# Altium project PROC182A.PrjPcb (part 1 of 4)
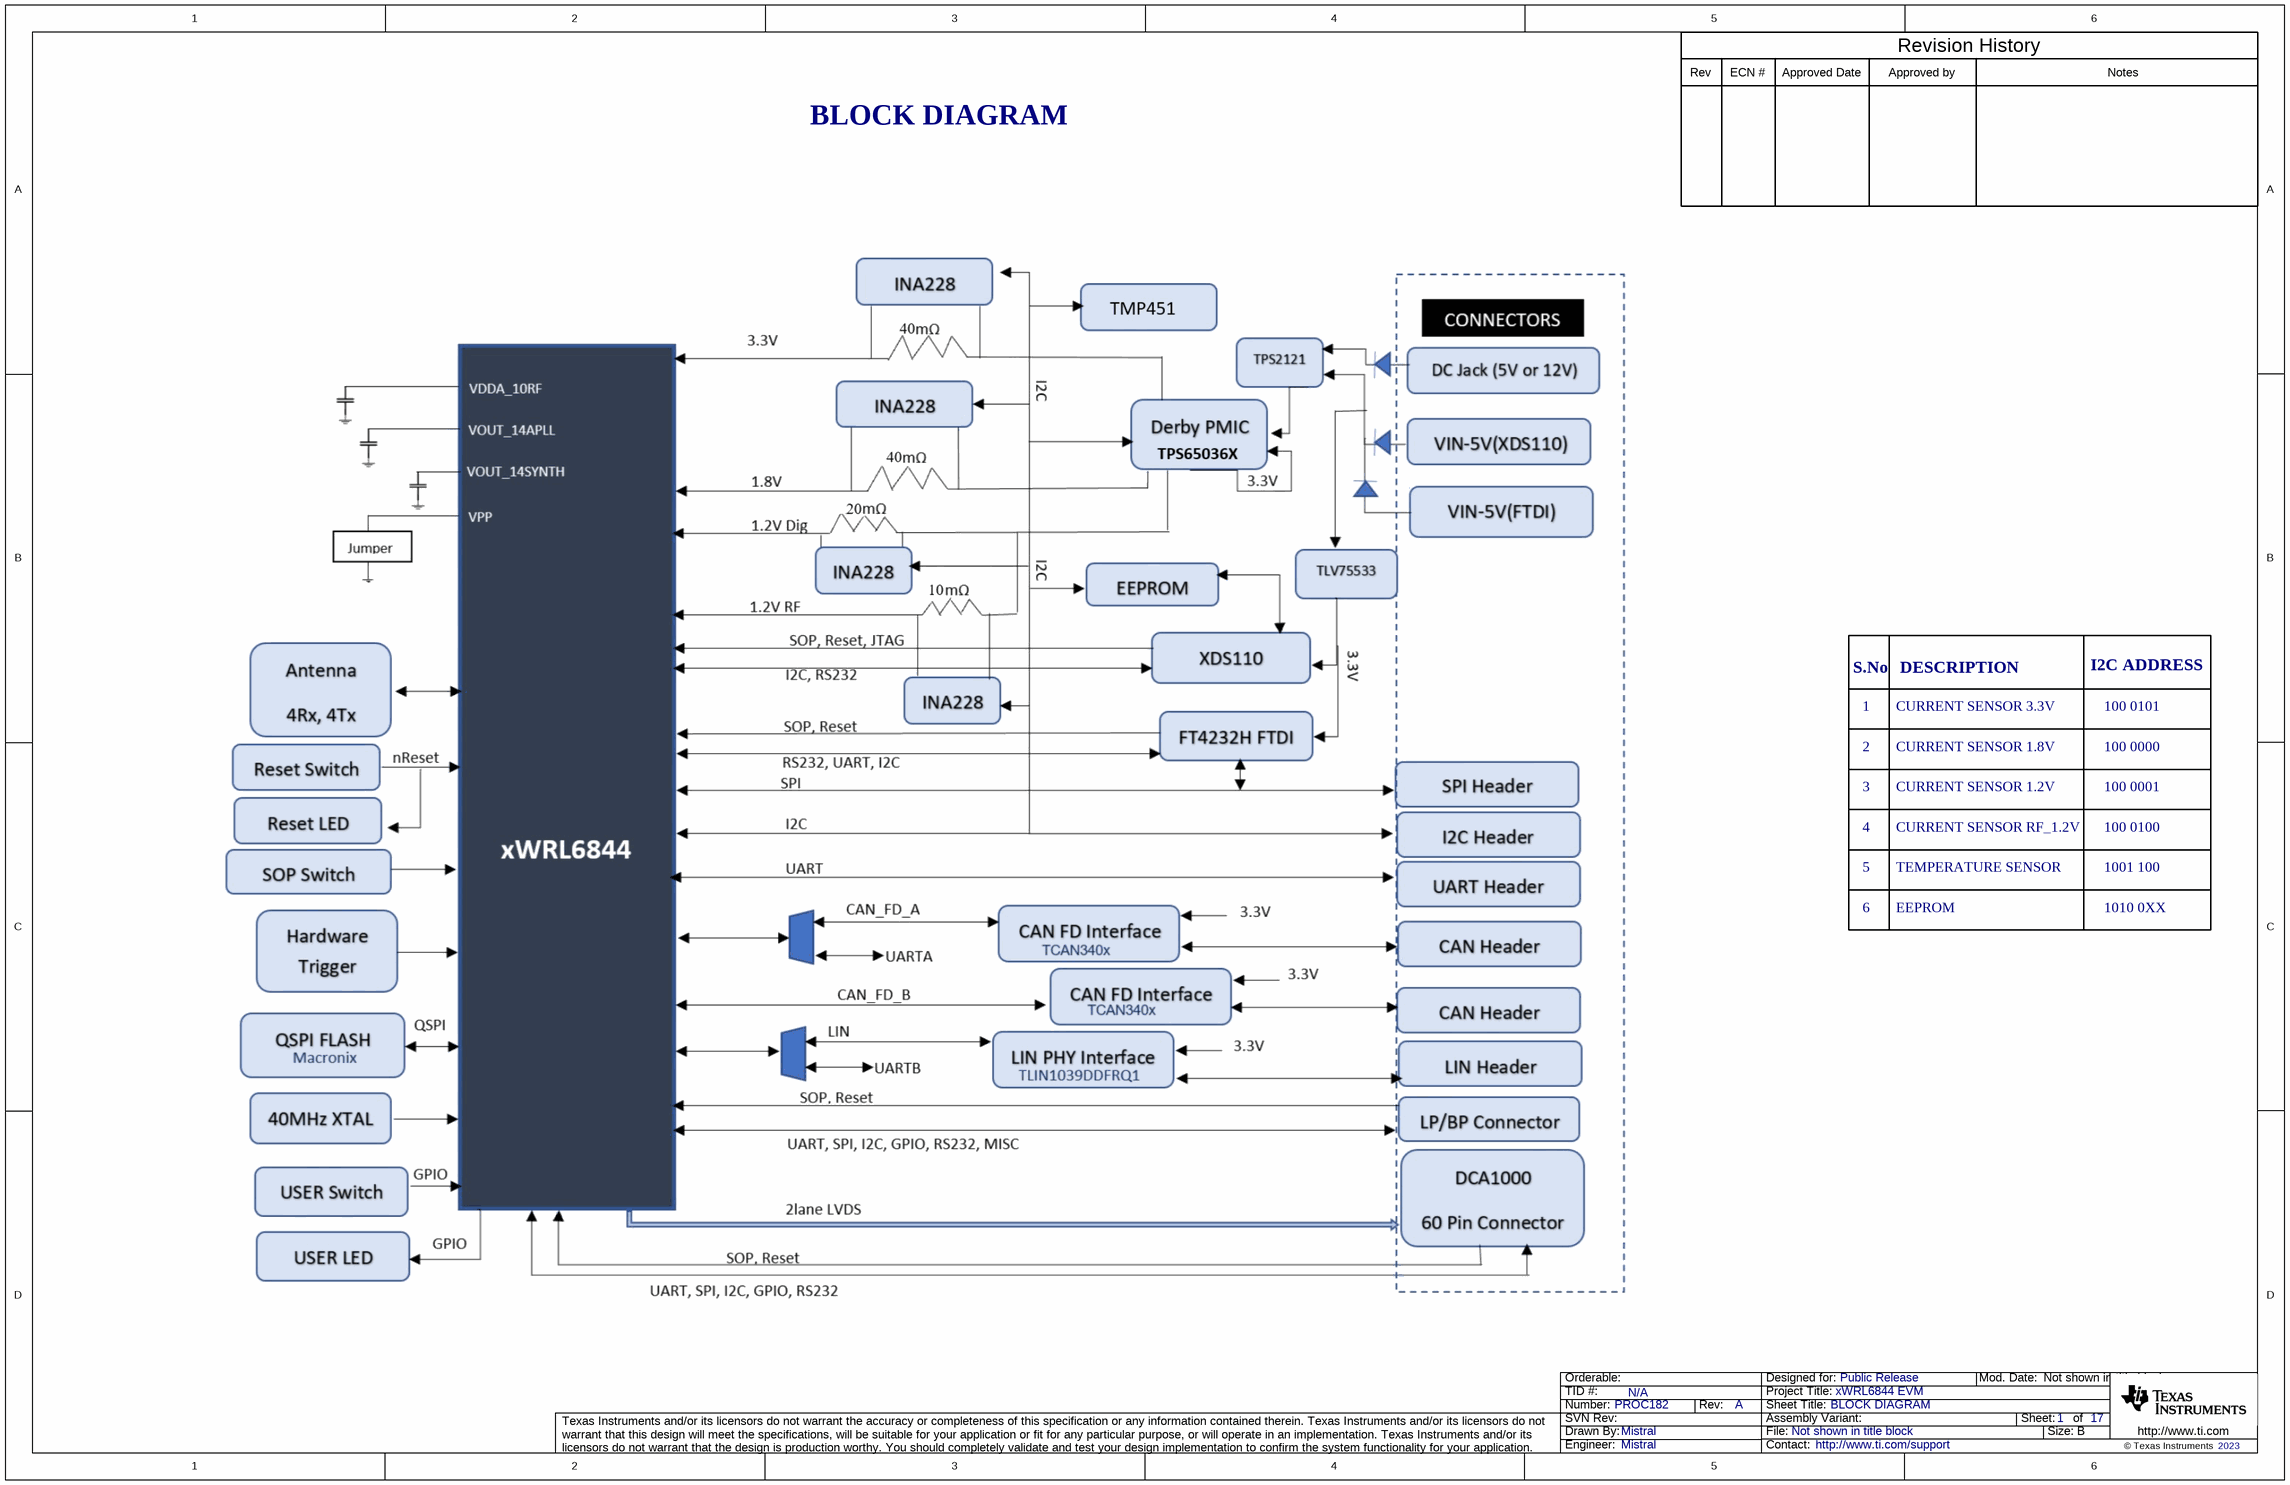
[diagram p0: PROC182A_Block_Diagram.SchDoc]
CopyrightYear: 2023; PCB_Layout: Mistral; PCB_Rev: A; PRJ_Customer: Public Release; PRJ_Engineer: Mistral; PRJ_Number: PROC182; PRJ_Title: xWRL6844 EVM; SCH_Rev: A; TechSupport: http://www.ti.com/support; TID: N/A
17 sheets, 568 parts. Net scope: flat (ports and power ports of the same name join across sheets).
Board file: PROC182A_PCB.PcbDoc
Sheets:
  PROC182A_Block_Diagram.SchDoc
  PROC182A_MUX_Block_Diagram.SchDoc
  PROC182A_Table_Of_Contents.SchDoc
  PROC182A_USB_PWR_DC_Jack_Switch.SchDoc
  PROC182A_PMIC.SchDoc
  PROC182A_Chip.SchDoc
  PROC182A_Decoupling_caps- QSPI Flash.SchDoc
  PROC182A_Temp_Current_sensors_EPROM.SchDoc
  PROC182A_Analog_Mux_SOP_Ctrl.SchDoc
  PROC182A_Analog_MUX_SPI.SchDoc
  PROC182A_XDS110_Interface.SchDoc
  PROC182A_MUX_CAN_FD.SchDoc
  PROC182A_CAN_LIN_PHY_Interface.SchDoc
  PROC182A_FTDI.SchDoc
  PROC182A_DCA1000_Connector_Reset.SchDoc
  PROC182A_I2C_SPI_Connector.SchDoc
  PROC182A_EVM_Hardware.SchDoc

## Sheet PROC182A_Block_Diagram.SchDoc: BLOCK DIAGRAM
size 431 x 279 mm; Date: Not shown in title block; ApprovedBy: Not shown in title block; CheckedBy: Not shown in title block; Author: Not shown in title block; CompanyName: Not shown in title block; DrawnBy: Mistral; Organization: Not shown in title block; Address1: Not shown in title block; Address2: Not shown in title block; Address3: Not shown in title block; Address4: Not shown in title block; DocumentNumber: 1; Revision: Use project parameter SCH_Rev; SheetNumber: 1; SheetTotal: 17; PageSetup: Record=PageOptions¦CenterHorizontal=True¦CenterVertical=True¦PrintScale=1.00¦XCorrection=1.00¦YCorrection=1.00¦PrintKind=0¦BorderSize=5000000¦LeftOffset=0¦BottomOffset=0¦Orientation=2¦PaperLength=1000¦PaperWidth=1000¦Scale=100¦PaperSource=15¦PrintQuality=600¦MediaType=1¦DitherType=10¦PaperKind=Letter¦PrintScaleMode=1

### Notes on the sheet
- Rev
- ECN #
- Approved Date
- Approved by
- Revision History
- Notes
- BLOCK DIAGRAM
- S.No
- DESCRIPTION
- I2C ADDRESS
- 1
- 2
- CURRENT SENSOR 3.3V
- CURRENT SENSOR 1.8V
- 100 0000
- 100 0101
- 3
- 4
- CURRENT SENSOR 1.2V
- CURRENT SENSOR RF_1.2V
- 100 0001
- 100 0100
- 5
- TEMPERATURE SENSOR
- 1001 100
- 6
- EEPROM
- 1010 0XX

## Sheet PROC182A_MUX_Block_Diagram.SchDoc: MUX BLOCK DIAGRAM
size 431 x 279 mm; Date: Not shown in title block; ApprovedBy: Not shown in title block; CheckedBy: Not shown in title block; Author: Not shown in title block; CompanyName: Not shown in title block; DrawnBy: Mistral; Engineer: Not shown in title block; Organization: Not shown in title block; Address1: Not shown in title block; Address2: Not shown in title block; Address3: Not shown in title block; Address4: Not shown in title block; DocumentNumber: 2; Revision: Use project parameter SCH_Rev; SheetNumber: 2; SheetTotal: 17; PageSetup: Record=PageOptions¦CenterHorizontal=True¦CenterVertical=True¦PrintScale=1.00¦XCorrection=1.00¦YCorrection=1.00¦PrintKind=0¦BorderSize=5000000¦LeftOffset=0¦BottomOffset=0¦Orientation=2¦PaperLength=1000¦PaperWidth=1000¦Scale=100¦PaperSource=15¦PrintQuality=600¦MediaType=1¦DitherType=10¦PaperKind=Letter¦PrintScaleMode=1
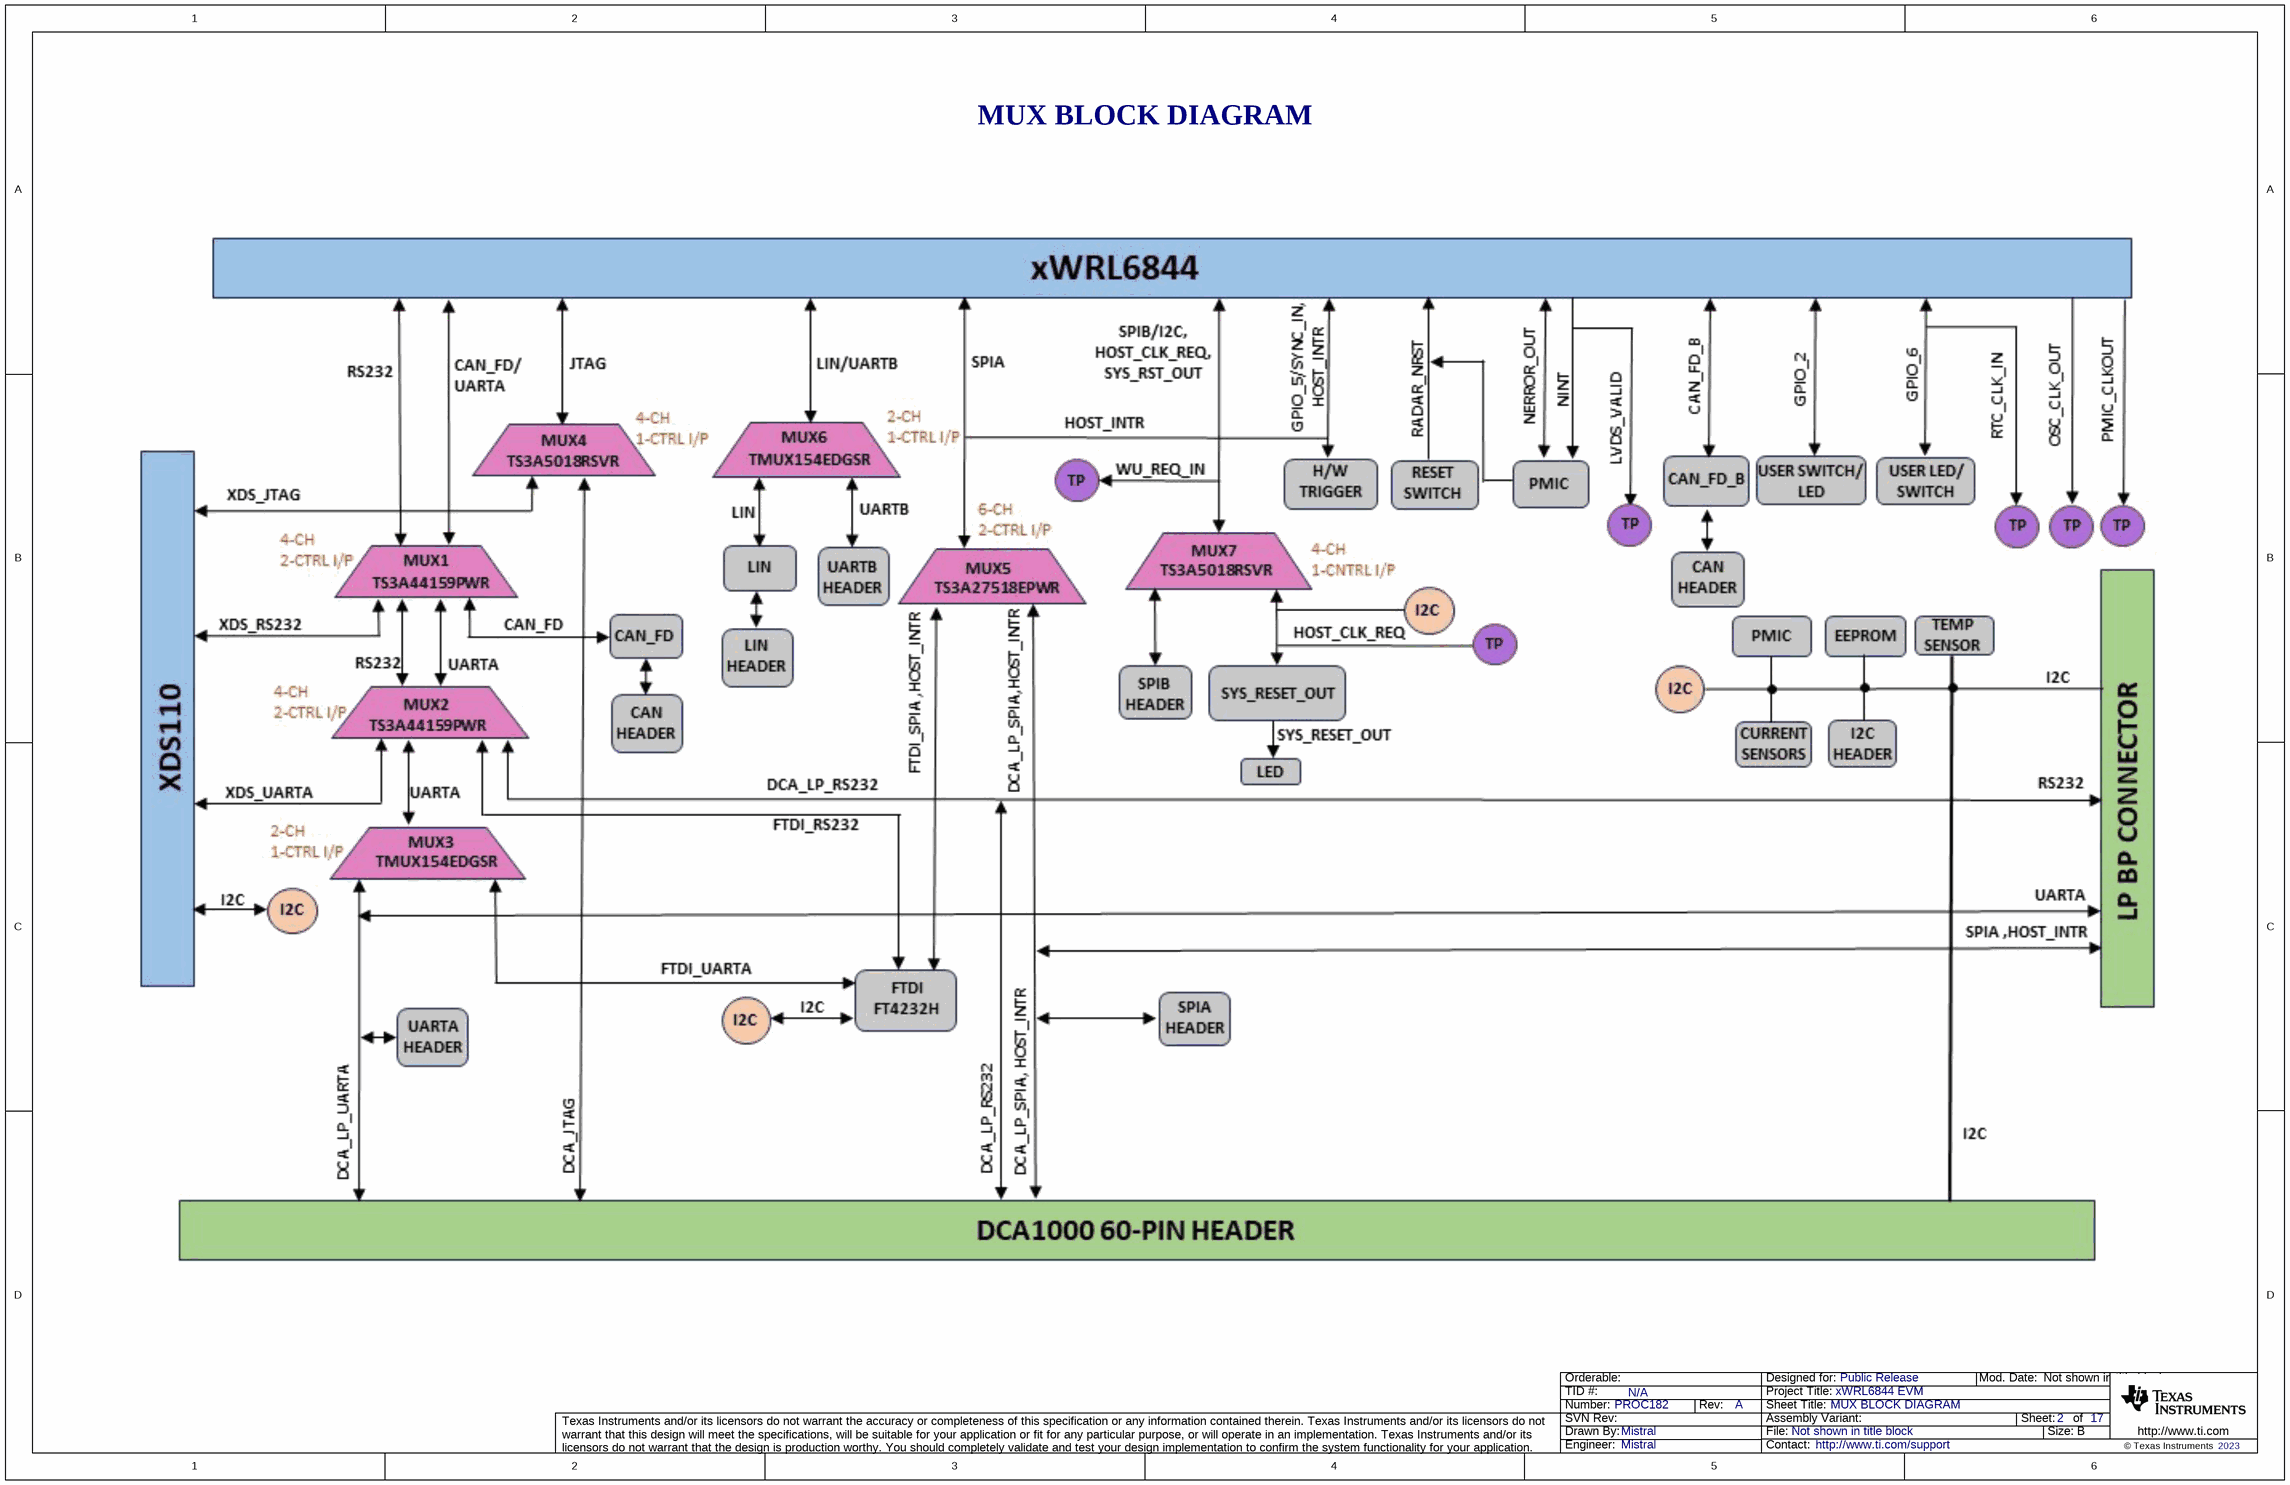
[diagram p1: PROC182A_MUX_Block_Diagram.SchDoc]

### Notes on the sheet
- MUX BLOCK DIAGRAM

## Sheet PROC182A_Table_Of_Contents.SchDoc: TABLE OF CONTENTS
size 431 x 279 mm; Date: Not shown in title block; ApprovedBy: Not shown in title block; CheckedBy: Not shown in title block; Author: Not shown in title block; CompanyName: Not shown in title block; DrawnBy: Mistral; Engineer: Not shown in title block; Organization: Not shown in title block; Address1: Not shown in title block; Address2: Not shown in title block; Address3: Not shown in title block; Address4: Not shown in title block; DocumentNumber: 3; Revision: Use project parameter SCH_Rev; SheetNumber: 3; SheetTotal: 16; PageSetup: Record=PageOptions¦CenterHorizontal=True¦CenterVertical=True¦PrintScale=1.00¦XCorrection=1.00¦YCorrection=1.00¦PrintKind=0¦BorderSize=5000000¦LeftOffset=0¦BottomOffset=0¦Orientation=2¦PaperLength=1000¦PaperWidth=1000¦Scale=100¦PaperSource=15¦PrintQuality=600¦MediaType=1¦DitherType=10¦PaperKind=Letter¦PrintScaleMode=1
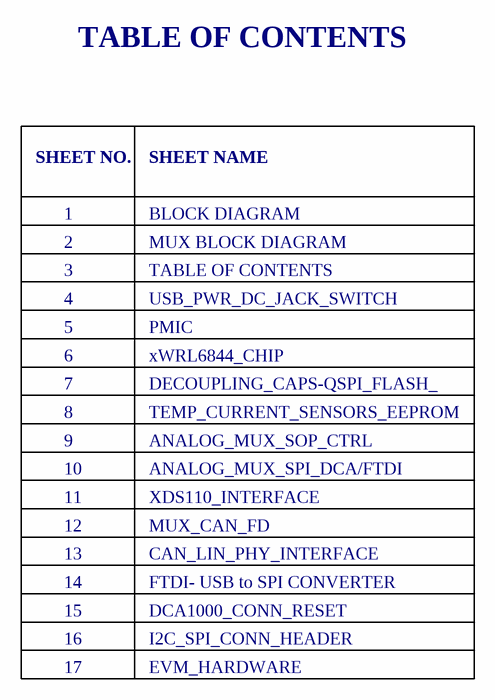
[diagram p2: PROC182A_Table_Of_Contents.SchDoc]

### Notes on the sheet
- TABLE OF CONTENTS
- SHEET NO.
- SHEET NAME
- 1
- 2
- 3
- BLOCK DIAGRAM
- MUX BLOCK DIAGRAM
- 4
- 5
- USB_PWR_DC_JACK_SWITCH
- PMIC
- 7
- 8
- 6
- DECOUPLING_CAPS-QSPI_FLASH_
- TEMP_CURRENT_SENSORS_EEPROM
- xWRL6844_CHIP
- 10
- 9
- ANALOG_MUX_SOP_CTRL
- ANALOG_MUX_SPI_DCA/FTDI
- 11
- 12
- 13
- XDS110_INTERFACE
- CAN_LIN_PHY_INTERFACE
- MUX_CAN_FD
- 14
- 15
- DCA1000_CONN_RESET
- FTDI- USB to SPI CONVERTER
- 16
- 17
- I2C_SPI_CONN_HEADER
- EVM_HARDWARE

## Sheet PROC182A_USB_PWR_DC_Jack_Switch.SchDoc: USB_PWR_DC_JACK_SWITCH
size 431 x 279 mm; Date: Not shown in title block; ApprovedBy: Not shown in title block; CheckedBy: Not shown in title block; Author: Not shown in title block; CompanyName: Not shown in title block; DrawnBy: Mistral; Engineer: Not shown in title block; Organization: Not shown in title block; Address1: Not shown in title block; Address2: Not shown in title block; Address3: Not shown in title block; Address4: Not shown in title block; DocumentNumber: 4; Revision: Use project parameter SCH_Rev; SheetNumber: 4; SheetTotal: 17; PageSetup: Record=PageOptions¦CenterHorizontal=True¦CenterVertical=True¦PrintScale=1.00¦XCorrection=1.00¦YCorrection=1.00¦PrintKind=0¦BorderSize=5000000¦LeftOffset=0¦BottomOffset=0¦Orientation=2¦PaperLength=1000¦PaperWidth=1000¦Scale=100¦PaperSource=15¦PrintQuality=600¦MediaType=1¦DitherType=10¦PaperKind=Letter¦PrintScaleMode=1
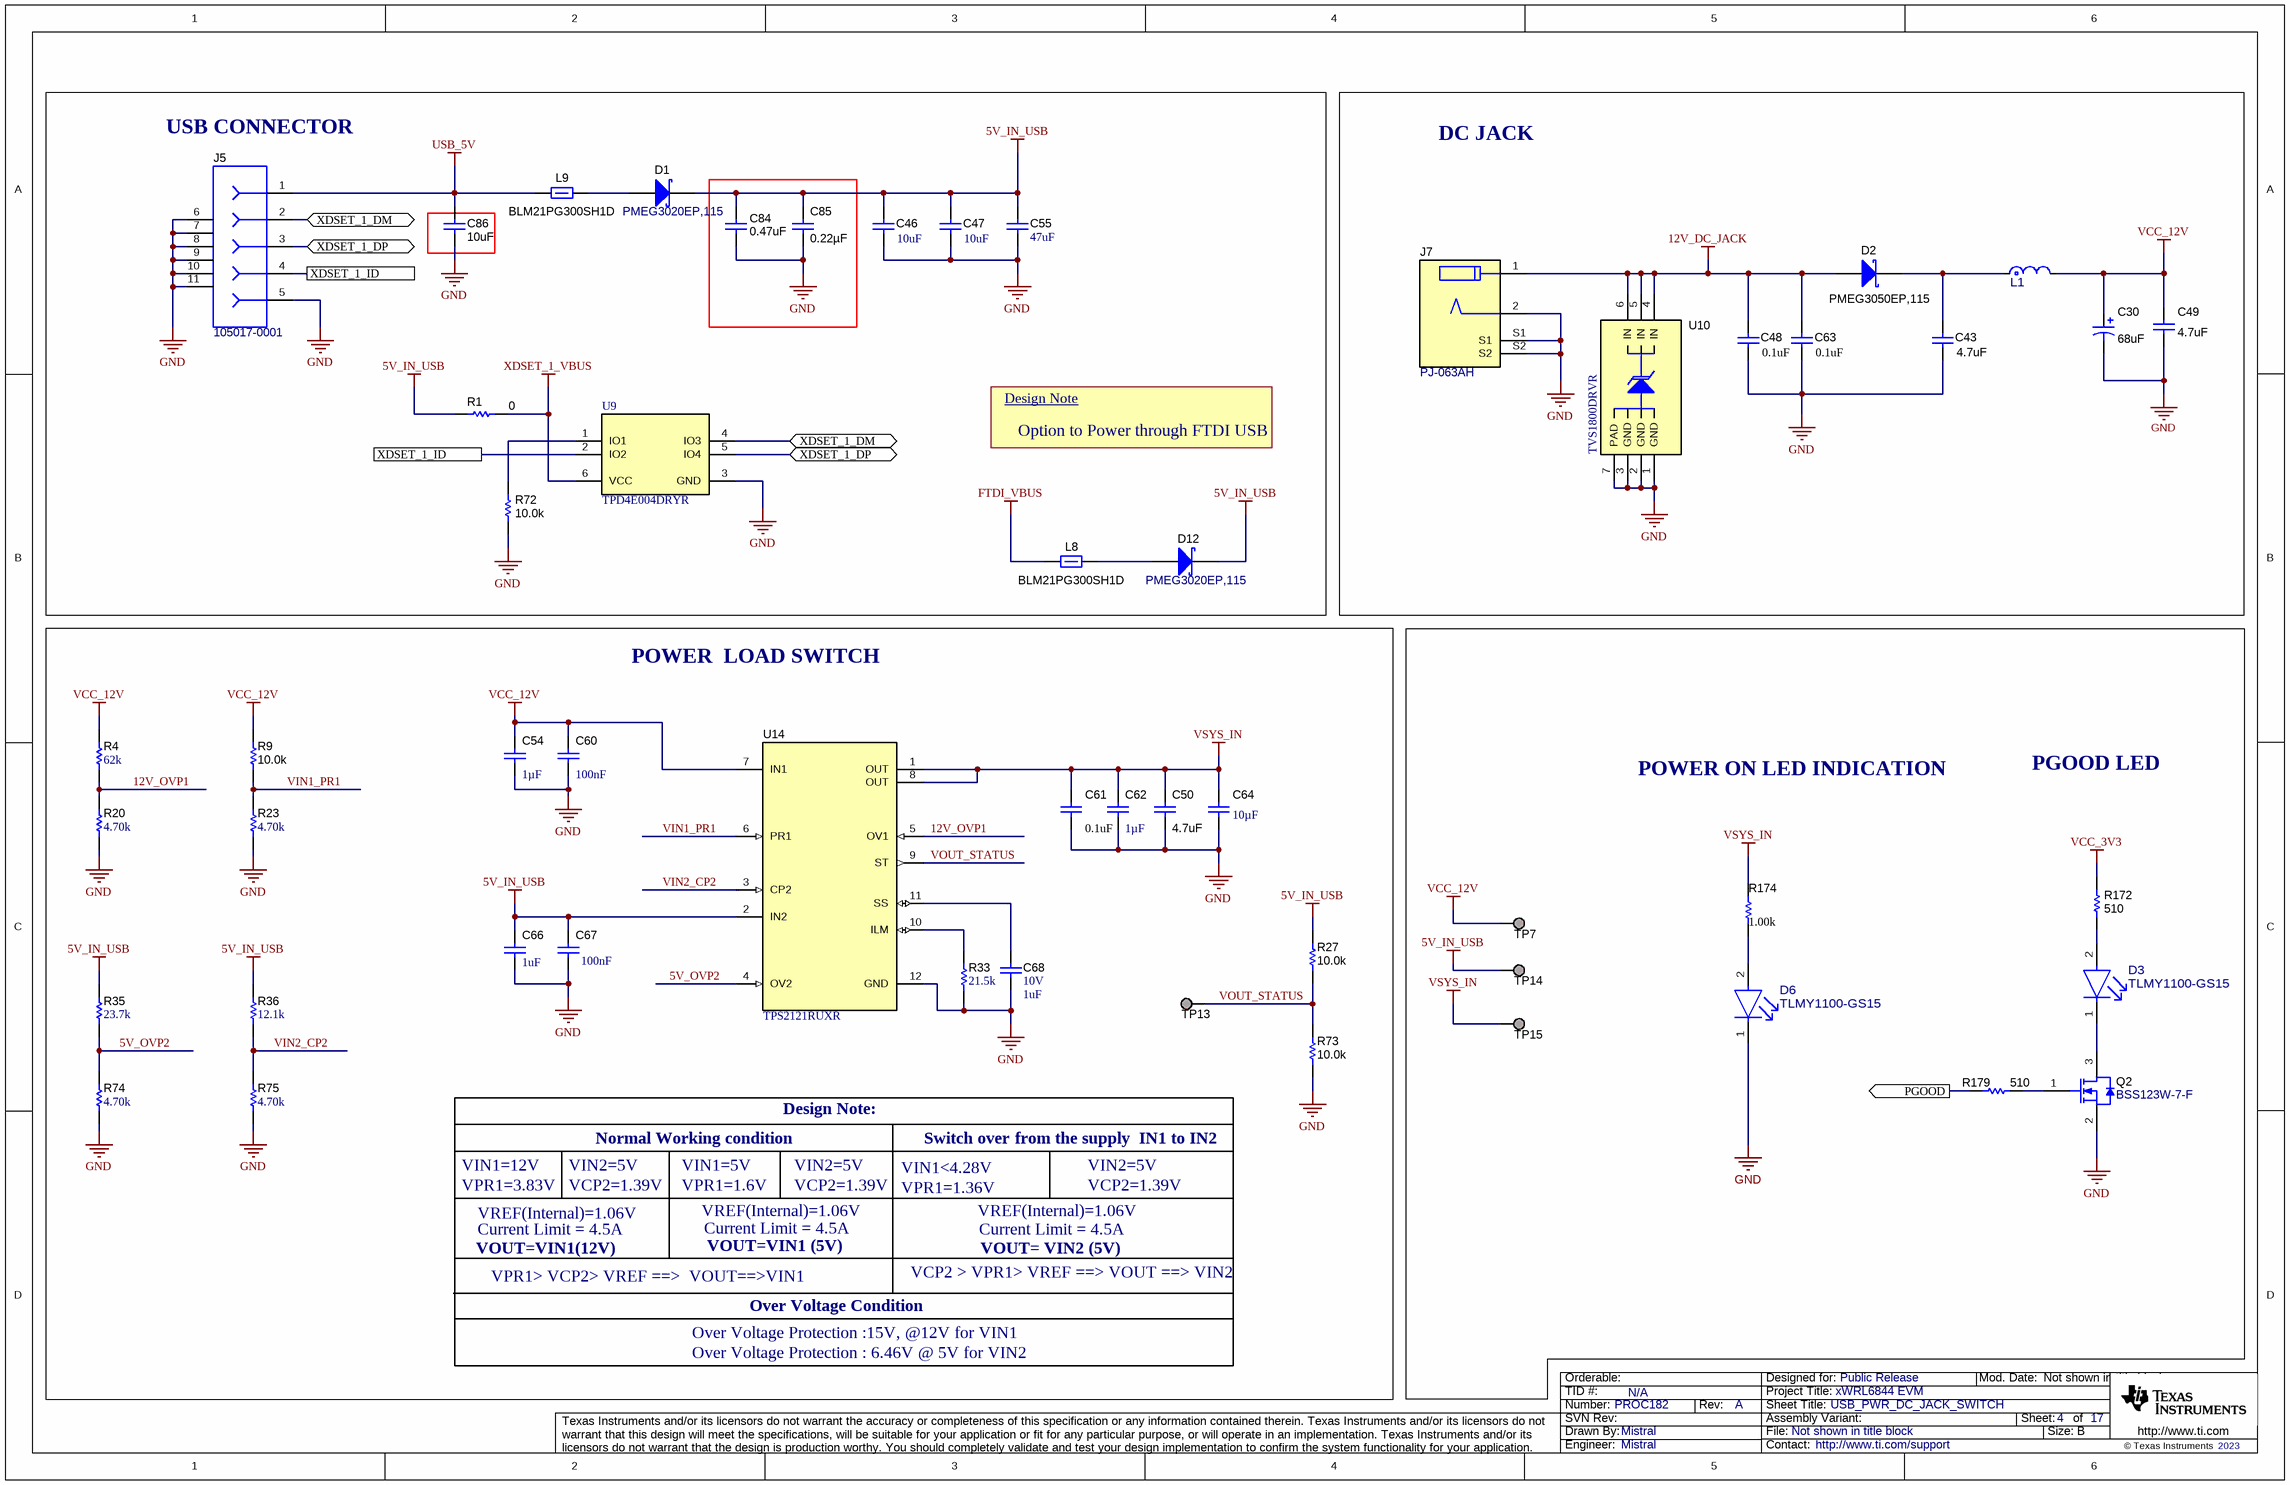
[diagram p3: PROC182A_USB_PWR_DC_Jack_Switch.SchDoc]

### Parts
C30  ValueDisplayed: 68uF  [SM_RADIAL_6.3BMM]  (hidden comment: EEHZC1V680XP)
C43  ValueDisplayed: 4.7uF  [1206_180L]  (hidden comment: C3216X7R1H475K160AC)
C46  ValueDisplayed: 10uF  [0402]  (hidden comment: GRM155R61A106ME11D)
C47  ValueDisplayed: 10uF  [0402]  (hidden comment: GRM155R61A106ME11D)
C48  ValueDisplayed: 0.1uF  [0402]  (hidden comment: GCM155R71H104KE02D)
C49  ValueDisplayed: 4.7uF  [1206_180L]  (hidden comment: C3216X7R1H475K160AC)
C50  ValueDisplayed: 4.7uF  [1206_180L]  (hidden comment: C3216X7R1H475K160AC)
C54  Cap_F: 1µF  [0603]  (hidden comment: CL10B105KA8NNNC)
C55  ValueDisplayed: 47uF  [1206_180]  (hidden comment: GRM31CR61A476KE15L)
C60  Cap_F: 100nF  [0402]  (hidden comment: GCM155R71H104KE02D)
C61  ValueDisplayed: 0.1uF  [0402]  (hidden comment: GCM155R71H104KE02D)
C62  Cap_F: 1µF  [0603]  (hidden comment: CL10B105KA8NNNC)
C63  ValueDisplayed: 0.1uF  [0402]  (hidden comment: GCM155R71H104KE02D)
C64  ValueDisplayed: 10µF  [1206_180]  (hidden comment: C1206C106J3RACAUTO)
C66  ValueDisplayed: 1uF  [0402_070]  (hidden comment: GCM155C71A105KE38D)
C67  Cap_F: 100nF  [0402]  (hidden comment: GCM155R71H104KE02D)
C68  VDC_V: 10V  ValueDisplayed: 1uF  [0402_070]  (hidden comment: GCM155C71A105KE38D)
C84  ValueDisplayed: 0.47uF  [0402L]  (hidden comment: GCM155C71A474KE36D)
C85  ValueDisplayed: 0.22µF  [0402L]  (hidden comment: GCM155R71C224KE02D)
C86  ValueDisplayed: 10uF  [0603S]  (hidden comment: GRT188R61A106KE13D)
D1  PMEG3020EP,115  [SOD-128]
D2  PMEG3050EP,115  [SOD-128]
D3  TLMY1100-GS15  [FP-TLMY1100-GS15_0603-MFG]
D6  TLMY1100-GS15  [FP-TLMY1100-GS15_0603-MFG]
D12  PMEG3020EP,115  [SOD-128]
J5  105017-0001  [CONN_105017-0001]
J7  PJ-063AH  [CUI_PJ-063AH]
L1  XGL5050-472MEC  [FP-XGL5050-472MEC_SMT2_5MM28_5MM48-MFG]  (value not drawn)
L8  BLM21PG300SH1D  [0805]
L9  BLM21PG300SH1D  [0805]
Q2  BSS123W-7-F  [SOT-323]
R1  ValueDisplayed: 0  [0603]  (hidden comment: MCT06030Z0000ZP500)
R4  ValueDisplayed: 62k  [0402]  (hidden comment: CRCW040262K0JNED)
R9  ValueDisplayed: 10.0k  [0402L]  (hidden comment: CRCW040210K0FKED)
R20  ValueDisplayed: 4.70k  [0402]  (hidden comment: RC0402FR-074K7L)
R23  ValueDisplayed: 4.70k  [0402]  (hidden comment: RC0402FR-074K7L)
R27  ValueDisplayed: 10.0k  [0402L]  (hidden comment: CRCW040210K0FKED)
R33  ValueDisplayed: 21.5k  [0402]  (hidden comment: CRCW040221K5FKED)
R35  ValueDisplayed: 23.7k  [0402]  (hidden comment: CRCW040223K7FKED)
R36  ValueDisplayed: 12.1k  [0603]  (hidden comment: RT0603BRD0712K1L)
R72  ValueDisplayed: 10.0k  [0402L]  (hidden comment: CRCW040210K0FKED)
R73  ValueDisplayed: 10.0k  [0402L]  (hidden comment: CRCW040210K0FKED)
R74  ValueDisplayed: 4.70k  [0402]  (hidden comment: RC0402FR-074K7L)
R75  ValueDisplayed: 4.70k  [0402]  (hidden comment: RC0402FR-074K7L)
R172  ValueDisplayed: 510  [0402L]  (hidden comment: ERJ-2GEJ511X)
R174  ValueDisplayed: 1.00k  [0402]  (hidden comment: ERJ-2RKF1001X)
R179  ValueDisplayed: 510  [0402L]  (hidden comment: ERJ-2GEJ511X)
TP7  TESTPOINT  [TP_25MIL-SMT]  (value not drawn)  (no BOM)
TP13  TESTPOINT  [TP_25MIL-SMT]  (value not drawn)  (no BOM)
TP14  TESTPOINT  [TP_25MIL-SMT]  (value not drawn)  (no BOM)
TP15  TESTPOINT  [TP_25MIL-SMT]  (value not drawn)  (no BOM)
U9  TPD4E004DRYR  [DRY0006A]
U10  TVS1800DRVR  [DRV0006A]
U14  TPS2121RUXR  [RUX0012A]

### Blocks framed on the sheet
USB CONNECTOR: C46 C47 C55 C84-C86 D1 D12 J5 L8 L9 R1 R72 U9
DC JACK: C30 C43 C48 C49 C63 D2 J7 L1 U10
POWER  LOAD SWITCH: C50 C54 C60-C62 C64 C66-C68 R4 R9 R20 R23 R27 R33 R35 R36 R73-R75 TP13 U14

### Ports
PGOOD (out), XDSET_1_DM (bidir), XDSET_1_DP (bidir), XDSET_1_ID

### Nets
5V_IN_USB: C46.2 C47.1 C55.1 C66.1 C67.2 C84.1 C85.2 D1.1(K) D12.1(K) R1.2 R27.1 R35.2 R36.2 TP14.1 U14.2(IN2)
12V_DC_JACK: C48.1 C63.1 D2.2(A) J7.1 U10.4(IN) U10.5(IN) U10.6(IN)
FTDI_VBUS: L8.1
GND: C30.2(-) C43.2 C46.1 C47.2 C48.2 C49.2 C50.2 C54.2 C55.2 C60.2 C61.2 C62.2 C63.2 C64.2 C66.2 C67.1 C68.2 C84.2 C85.1 C86.1 D6.1(C) J5.5 J5.6 J5.7 J5.8 J5.9 J5.10 J5.11 J7.2 J7.S1 J7.S2 Q2.2(S) R20.1 R23.1 R33.1 R72.1 R73.2 R74.1 R75.1 U9.3(GND) U10.1(GND) U10.2(GND) U10.3(GND) U10.7(PAD) U14.12(GND)
USB_5V: C86.2 J5.1 L9.1
VCC_3V3: R172.2
VCC_12V: C30.1(+) C49.1 C54.1 C60.1 L1.2 R4.2 R9.1 TP7.1 U14.7(IN1)
VSYS_IN: C50.1 C61.1 C62.1 C64.1 R174.1 TP15.1 U14.1(OUT) U14.8(OUT)
XDSET_1_VBUS: R1.1 U9.6(VCC)
5V_OVP2: R35.1 R74.2 U14.4(OV2)
12V_OVP1: R4.1 R20.2 U14.5(OV1)
PGOOD: R179.1 ; port PGOOD
VIN1_PR1: R9.2 R23.2 U14.6(PR1)
VIN2_CP2: R36.1 R75.2 U14.3(CP2)
VOUT_STATUS: R27.2 R73.1 TP13.1 U14.9(ST)
XDSET_1_DM: J5.2 U9.4(IO3) ; port XDSET_1_DM
XDSET_1_DP: J5.3 U9.5(IO4) ; port XDSET_1_DP
XDSET_1_ID: J5.4 U9.2(IO2) ; port XDSET_1_ID
NetC43_1: C43.1 D2.1(K) L1.1
NetC68_1: C68.1 U14.11(SS)
NetD1_2: D1.2(A) L9.2
NetD3_1: D3.1(C) Q2.3(D)
NetD3_2: D3.2(A) R172.1
NetD6_2: D6.2(A) R174.2
NetD12_2: D12.2(A) L8.2
NetQ2_1: Q2.1(G) R179.2
NetR33_2: R33.2 U14.10(ILM)
NetR72_2: R72.2 U9.1(IO1)

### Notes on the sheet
- Design Note
- Option to Power through FTDI USB
- POWER ON LED INDICATION
- PGOOD LED
- Design Note:
- VIN1=12V
- VIN2=5V
- Normal Working condition
- VIN1=5V
- VIN1<4.28V
- Switch over
- from the supply  IN1 to IN2
- VPR1=3.83V
- Current Limit = 4.5A
- VREF(Internal)=1.06V
- VCP2=1.39V
- VPR1=1.6V
- VOUT=VIN1 (5V)
- VPR1=1.36V
- VOUT=VIN1(12V)
- VPR1> VCP2> VREF ==>  VOUT==>VIN1
- Over Voltage Condition
- VCP2 > VPR1> VREF ==> VOUT ==> VIN2
- VOUT= VIN2 (5V)
- Over Voltage Protection :15V, @12V for VIN1
- Over Voltage Protection : 6.46V @ 5V for VIN2

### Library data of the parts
C30 = CMP-0012608-3: CAP, Polymer Hybrid, 68 uF, 35 V, +/- 20%, 35 ohm, 6.3x7.7 SMD; Manufacturer: Panasonic; TaMin_C: -55°C; ESR_ohm: 35; Polarized: Y; SizeAreaWB_mm2: 79.98; Value1: 35 ohm; Value: 68uF; TaMax_C: 125°C; SizeZ_mm: 7.7; SizeX_mm: 7.3; SizeY_mm: 6.6; Value2: 35V; SizeArea_mm2: 48.18; CompType: Capacitor; Cap_F: 68µF; IRMS_A: 1.4A; AEC Category: Q200
C43 C49 C50 = CMP-0008702-2: CAP, CERM, 4.7 uF, 50 V, +/- 10%, X7R, 1206; Manufacturer: TDK; TaMin_C: -55°C; ESR_ohm: 3.158m; Polarized: N; SizeAreaWB_mm2: 10.92; Value1: 0.003158 ohm; U/M: EA; Value: 4.7uF; TaMax_C: 125°C; SizeZ_mm: 1.8; SizeX_mm: 3.2; SizeY_mm: 1.6; Cap_Case: 1206_180; Value2: 50V; SizeArea_mm2: 5.12; Cap_F: 4.7µF; IRMS_A: 4.08379A; AEC Category: Q200
C46 C47 = CMP-0006564-3: CAP, CERM, 10 uF, 10 V, +/- 20%, X5R, 0402; Manufacturer: MuRata; TaMin_C: -55°C; Polarized: N; SizeAreaWB_mm2: 3; Value1: Unknown; U/M: EA; Value: 10uF; TaMax_C: 85°C; SizeZ_mm: 0.6; SizeX_mm: 1; SizeY_mm: 0.5; Value2: 10V; Cap_F: 10µF; AEC Category: Q200
C48 C61 C63 = CMP-0006356-2: CAP, CERM, 0.1 uF, 50 V, +/- 10%, X7R, AEC-Q200 Grade 1, 0402; Manufacturer: MuRata; TaMin_C: -55°C; Polarized: N; SizeAreaWB_mm2: 3; Value1: Unknown; U/M: EA; Value: 0.1uF; TaMax_C: 125°C; SizeZ_mm: 0.6; SizeX_mm: 1; SizeY_mm: 0.5; Value2: 50V; AEC Qualified: Y; Cap_F: 100nF; AEC Category: Q200
C54 C62 = CMP-0086540-3: CAP, 1uF, 25V, ±10%, X7R, 0603; Manufacturer: Samsung; TempCo: 15%; SizeZ_mm: 0.9mm; AEC Qualified: No; Symbol Name: SYM-CL10B105KA8NNNC
C55 = CMP-0008944-2: CAP, CERM, 47 uF, 10 V, +/- 10%, X5R, 1206; Manufacturer: MuRata; TaMin_C: -55°C; Polarized: N; SizeAreaWB_mm2: 10.92; Value1: Unknown; U/M: EA; Value: 47uF; TaMax_C: 85°C; SizeZ_mm: 1.8; SizeX_mm: 3.2; SizeY_mm: 1.6; Cap_Case: 1206; Value2: 10V; SizeArea_mm2: 5.12; Cap_F: 47µF; AEC Category: Q200
C60 C67 = CMP-0006356-2: CAP, CERM, 0.1 uF, 50 V, +/- 10%, X7R, AEC-Q200 Grade 1, 0402; Manufacturer: MuRata; AEC Qualified: Y; SizeZ_mm: 0.6; VDC_V: 50V; AEC Category: Q200; AEC Grade: 1; Polarized: N; SizeArea_mm2: 0.5; SizeAreaWB_mm2: 3; TaMax_C: 125°C; TaMin_C: -55°C; U/M: EA; Value1: Unknown; Value: 0.1uF
C64 = CMP-0081062-1: CAP, CERM, 10 µF, 25 V,+/- 5%, X7R, AEC-Q200 Grade 1, 1206; Manufacturer: Kemet; TaMin_C: -55°C; Polarized: N; SizeAreaWB_mm2: 10.92; U/M: EA; Value: 10uF; TaMax_C: 125°C; SizeZ_mm: 1.8; SizeX_mm: 3.2; SizeY_mm: 1.6; Value2: 25V; SizeArea_mm2: 5.12; AEC Qualified: Y; AEC Grade: 1; AEC Category: Q200
C66 = CMP-0006349-2: CAP, CERM, 1 uF, 10 V, +/- 10%, X7S, AEC-Q200 Grade 1, 0402; Manufacturer: MuRata; Polarized: N; Value: 1uF; U/M: EA; Cap_F: 1µF; Value1: Unknown; VDC_V: 10V; TaMin_C: -55°C; TaMax_C: 125°C; Cap_Case: 0402; SizeArea_mm2: 0.5; SizeAreaWB_mm2: 3; SizeX_mm: 1; SizeZ_mm: 0.7; AEC Category: Q200; AEC Qualified: Y
C68 = CMP-0006349-2: CAP, CERM, 1 uF, 10 V, +/- 10%, X7S, AEC-Q200 Grade 1, 0402; Manufacturer: MuRata; TaMin_C: -55°C; Polarized: N; SizeAreaWB_mm2: 3; Value1: Unknown; U/M: EA; Value: 1uF; TaMax_C: 125°C; SizeZ_mm: 0.7; SizeX_mm: 1; SizeY_mm: 0.5; Cap_Case: 0402; AEC Qualified: Y; Cap_F: 1µF; AEC Category: Q200
C84 = CMP-0064967-2: CAP, CERM, 0.47 uF, 10 V,+/- 10%, X7S, 0402; Manufacturer: MuRata; Polarized: N; Value: 0.47uF; U/M: EA; Cap_F: 470nF; Value1: Unknown; VDC_V: 10V; TaMin_C: -55°C; TaMax_C: 125°C; Cap_Case: 0402; SizeArea_mm2: 0.5; SizeAreaWB_mm2: 3; SizeX_mm: 1; SizeZ_mm: 0.6; AEC Category: Q200
C85 = CMP-0078265-1: CAP, CERM, 0.22 µF, 16 V,+/- 10%, X7R, AEC-Q200 Grade 1, 0402; Manufacturer: MuRata; TaMin_C: -55°C; Polarized: N; SizeAreaWB_mm2: 3; U/M: EA; Value: 0.22uF; TaMax_C: 125°C; SizeZ_mm: 0.6; SizeX_mm: 1; SizeY_mm: 0.5; Cap_Case: 0402; Value2: 16V; CompType: Capacitor; AEC Qualified: Y; Cap_F: 220nF; AEC Category: Q200
C86 = CMP-0007497-5: CAP, CERM, 10 uF, 10 V, +/- 10%, X5R, 0603; Manufacturer: MuRata; Polarized: N; Value: 10uF; U/M: EA; Cap_F: 10µF; Tolerance_%: 20%; Value1: Unknown; VDC_V: 10V; TempCo: X7R; TaMin_C: -55°C; TaMax_C: 125°C; Cap_Case: 0603; SizeArea_mm2: 1.28; SizeAreaWB_mm2: 4.68; SizeX_mm: 1.6; SizeY_mm: 0.8; SizeZ_mm: 1; AEC Category: Q200
D1 D12 = CMP-0078758-2: Diode, Schottky, 30 V, 2 A, AEC-Q101, SOD-128; Manufacturer: Nexperia; Value2: 0.36V; SizeAreaWB_mm2: 19.6; Io_A: 2A; Value: 30V; AEC Qualified: Y; TJmax_C: 150°C; SizeX_mm: 4.6; AEC Category: Q101; SizeY_mm: 2.5; SizeArea_mm2: 11.5; Vf_V: 3.6dV; SizeZ_mm: 1.1
D2 = CMP-0077017-3: Diode, Schottky, 30 V, 5 A, SOD-128; Manufacturer: Nexperia; Vf_V: 360mV; Vr_V: 30V; Green_Lifecycle: Not Set; SizeZ_mm: 1.1; SizeY_mm: 2.5; Value2: 0.36V; Value1: 5A; SizeAreaWB_mm2: 19.6; AEC Category: Q101; SizeArea_mm2: 11.5; Green_REACh: Incomplete; TJmax_C: 150°C; SizeX_mm: 4.6; Value: 30V
D3 D6 = CMP-0121062-1: Yellow 589nm LED Indication - Discrete 2.1V 0603 (1608 Metric); Manufacturer: Vishay; Angle: 160°; LambdaP: 591nm; Power_TotalModule: 90mW; SizeZ_mm: 0.65mm; Tjmax_C: 120°C; Vr_V: 12V; AEC Grade: Grade 3; AEC Qualified: Yes; Forward Current: 20mA; Led Orientation: Top View; Luminous Intensity: 80mcd; TaMax_C: +100°C; TaMin_C: -40°C
J5 = CMP-0055293-1: Connector, Receptacle, Micro-USB Type B, R/A, Bottom Mount SMT; Manufacturer: Molex; CNHeader: FALSE; CompType: USB; CT: TRUE; Gender: Female; Green_Lifecycle: Active; Green_REACh: Passed
J7 = CMP-0079472-1: DC POWER JACK, R/A, TH; Manufacturer: CUI Inc.; Gender: Male; Cert_UL: Y; Current_A: 8A; Voltage_V: 24V
L1 = CMP-0094298-1: Shielded Power Inductor 4.7uH 16mOhms 9.7A; Manufacturer: Coilcraft; AEC Grade: Grade 1; TaMax_C: +125°C; Test Frequency: 1MHz; Ind_H: 4.7µH; TaMin_C: -40°C; DCR_ohm: 16m; Material: Composite; Self Resonant Frequency: 25MHz; SizeZ_mm: 5.1mm; Shrouded: true; Isat: 3.5A; Tolerance_%: 20%; AEC Qualified: Yes
L8 L9 = CMP-0003364-1: Ferrite Bead, 30 ohm @ 100 MHz, 4 A, 0805; Manufacturer: MuRata; ZTyp@100MHz_Ohm: 30; SizeAreaWB_mm2: 6.75; DCR_ohm: 14m; Value1: 0.014 ohm; Value: 30 ohm; Imax_A: 4A; SizeZ_mm: 1.45; SizeX_mm: 2; SizeY_mm: 1.25; SizeArea_mm2: 2.5
Q2 = CMP-0000948-2: MOSFET, N-CH, 100 V, 0.17 A, SOT-323; Alternate Manufacturer: None; Manufacturer: Diodes Inc.; SizeZ_mm: 1.1; ChType: N; Value1: 1; VdsMax_V: 100V; SizeX_mm: 2.2; Vgs_V: 20V; Value: 100V; Rdson45_ohm: 10; SizeArea_mm2: 4.84; AEC Category: Q101; IdsMax_A: 1.7dA; SizeAreaWB_mm2: 10.24; U/M: EA
R1 = CMP-0025884-3: RES, 0, 5%, 0.125 W, 0603; Manufacturer: Vishay/Beyschlag; Power_W: 125mW; TempCo: ppm/C; Value_Code: 0000; U/M: EA; Value: 0; EIA_Code: E24; SizeX_mm: 1.6; SizeY_mm: 0.8; SizeZ_mm: 1; Value2: 0.125W; SizeArea_mm2: 1.28; AEC Qualified: N; AEC Category: Q200
R4 = CMP-0026959-2: RES, 62 k, 5%, 0.063 W, 0402; Manufacturer: Vishay-Dale; Power_W: 63mW; TempCo: 200 ppm/C; Value_Code: 62k0; U/M: EA; Value: 62k; EIA_Code: E24; SizeX_mm: 1; SizeY_mm: 0.5; SizeZ_mm: 0.6; Value2: 0.063W; VDC_V: 50V; AEC Category: Q200
R9 R27 R72 R73 = CMP-0025958-3: RES, 10.0 k, 1%, 0.063 W, AEC-Q200 Grade 0, 0402; Manufacturer: Vishay-Dale; Power_W: 63mW; TempCo: 100 ppm/C; Value_Code: 10k0; Value: 10.0k; EIA_Code: E96; Res_ohm: 10k; SizeX_mm: 1; SizeY_mm: 0.5; SizeZ_mm: 0.6; Value2: 0.063W; AEC Qualified: Y; VDC_V: 50V; AEC Category: Q200; AEC Grade: 0
R20 R23 R74 R75 = CMP-0026739-1: RES, 4.70 k, 1%, 0.0625 W, 0402; Manufacturer: Yageo America; Power_W: 62.5mW; TempCo: 100 ppm/C; Value_Code: 4k70; U/M: EA; Value: 4.70k; Res_ohm: 4.7k; SizeX_mm: 1; SizeY_mm: 0.5; SizeZ_mm: 0.6; AEC Qualified: N; VDC_V: 50V; AEC Category: Q200
R33 = CMP-0026171-2: RES, 21.5 k, 1%, 0.063 W, AEC-Q200 Grade 0, 0402; Manufacturer: Vishay-Dale; Power_W: 63mW; TempCo: 100 ppm/C; Value_Code: 21k5; Value: 21.5k; EIA_Code: E96; SizeX_mm: 1; SizeY_mm: 0.5; SizeZ_mm: 0.6; Value2: 0.063W; AEC Qualified: Y; VDC_V: 50V; AEC Category: Q200; AEC Grade: 0
R35 = CMP-0026187-2: RES, 23.7 k, 1%, 0.063 W, AEC-Q200 Grade 0, 0402; Manufacturer: Vishay-Dale; Power_W: 63mW; TempCo: 100 ppm/C; Value_Code: 23k7; Value: 23.7k; EIA_Code: E96; SizeX_mm: 1; SizeY_mm: 0.5; SizeZ_mm: 0.6; Value2: 0.063W; AEC Qualified: Y; VDC_V: 50V; AEC Category: Q200; AEC Grade: 0
R36 = CMP-0023704-1: RES, 12.1 k, 0.1%, 0.1 W, 0603; Manufacturer: Yageo America; Power_W: 100mW; TempCo: 25 ppm/C; Value_Code: 12k1; U/M: EA; Value: 12.1k; EIA_Code: E192; SizeX_mm: 1.6; SizeY_mm: 0.8; SizeZ_mm: 1; Value2: 0.1W; SizeArea_mm2: 1.28; VDC_V: 75V; AEC Category: Q200
R172 R179 = CMP-0078212-1: RES, 510, 5%, 0.1 W, AEC-Q200 Grade 0, 0402; Manufacturer: Panasonic; Value_Code: 510R; SizeArea_mm2: 0.5; AEC Qualified: Y; AEC Category: Q200; Value: 510; SizeZ_mm: 0.6; EIA_Code: E24; TempCo: 200 ppm/C; AEC Grade: 0; Power_W: 100mW; VDC_V: 50V; Value2: 0.1W; U/M: EA; SizeX_mm: 1
R174 = CMP-0026657-1: RES, 1.00 k, 1%, 0.1 W, 0402; Manufacturer: Panasonic; Power_W: 100mW; TempCo: 100 ppm/C; Value_Code: 1k00; U/M: EA; Value: 1.00k; EIA_Code: E96; Res_ohm: 1k; SizeX_mm: 1; SizeY_mm: 0.5; SizeZ_mm: 0.6; Value2: 0.1W; VDC_V: 50V; AEC Category: Q200
TP7 TP13-TP15 = CMP-0078143-3: TEST POINT.  No entry in BOM.
U9 = CMP-0043115-3: 4-Channel ESD Protection Array for High-Speed Data Interfaces, DRY0006A (USON-6); Manufacturer: Texas Instruments; IO Leakage Current(nA): 1; USB High Speed: TRUE; IO Capacitance(Typ)(pF): 1.6; Eco-Plan: Green (RoHS & no Sb/Br); IEC 61000-4-2 Contact(+/- kV): 8; Breakdown Voltage(Min)(V): 6; IEC 61000-4-2 Air-Gap(+/- kV): 12; AEC Category: Q200; AEC Qualified: N; CompType: IC; SizeAreaWB_mm2: 4.9; SizeArea_mm2: 1.45; SizeX_mm: 1.0; SizeZ_mm: 0.6; Rating: Catalog
U10 = CMP-0077835-1: 18-V Precision Surge Protection Clamp, DRV0006A (WSON-6); Alternate Manufacturer: Texas Instruments; SizeAreaWB_mm2: 9.0; SizeZ_mm: 0.8; SizeX_mm: 2.0; SizeArea_mm2: 4.0; CompType: IC; AEC Qualified: N; AEC Category: Q200
U14 = CMP-0078351-3: 2.7V-22V, 4A, 50mohm Priority Power MUX, RUX0012A (VQFN-HR-12); Alternate PartNumber: TPS2121RUXT; Alternate Manufacturer: Texas Instruments; SizeAreaWB_mm2: 10.5; SizeZ_mm: 1; SizeX_mm: 2; SizeY_mm: 2.5; SizeArea_mm2: 5; CompType: IC; AEC Qualified: N; AEC Category: Q200

## Sheet PROC182A_PMIC.SchDoc: PMIC and LDOs
size 431 x 279 mm; Date: Not shown in title block; ApprovedBy: Not shown in title block; CheckedBy: Not shown in title block; Author: Not shown in title block; CompanyName: Not shown in title block; DrawnBy: Mistral; Engineer: Not shown in title block; Organization: Not shown in title block; Address1: Not shown in title block; Address2: Not shown in title block; Address3: Not shown in title block; Address4: Not shown in title block; DocumentNumber: 16; Revision: Use project parameter SCH_Rev; SheetNumber: 5; SheetTotal: 17; PageSetup: Record=PageOptions¦CenterHorizontal=True¦CenterVertical=True¦PrintScale=1.00¦XCorrection=1.00¦YCorrection=1.00¦PrintKind=0¦BorderSize=5000000¦LeftOffset=0¦BottomOffset=0¦Orientation=2¦PaperLength=1000¦PaperWidth=1000¦Scale=100¦PaperSource=15¦PrintQuality=600¦MediaType=1¦DitherType=10¦PaperKind=Letter¦PrintScaleMode=1
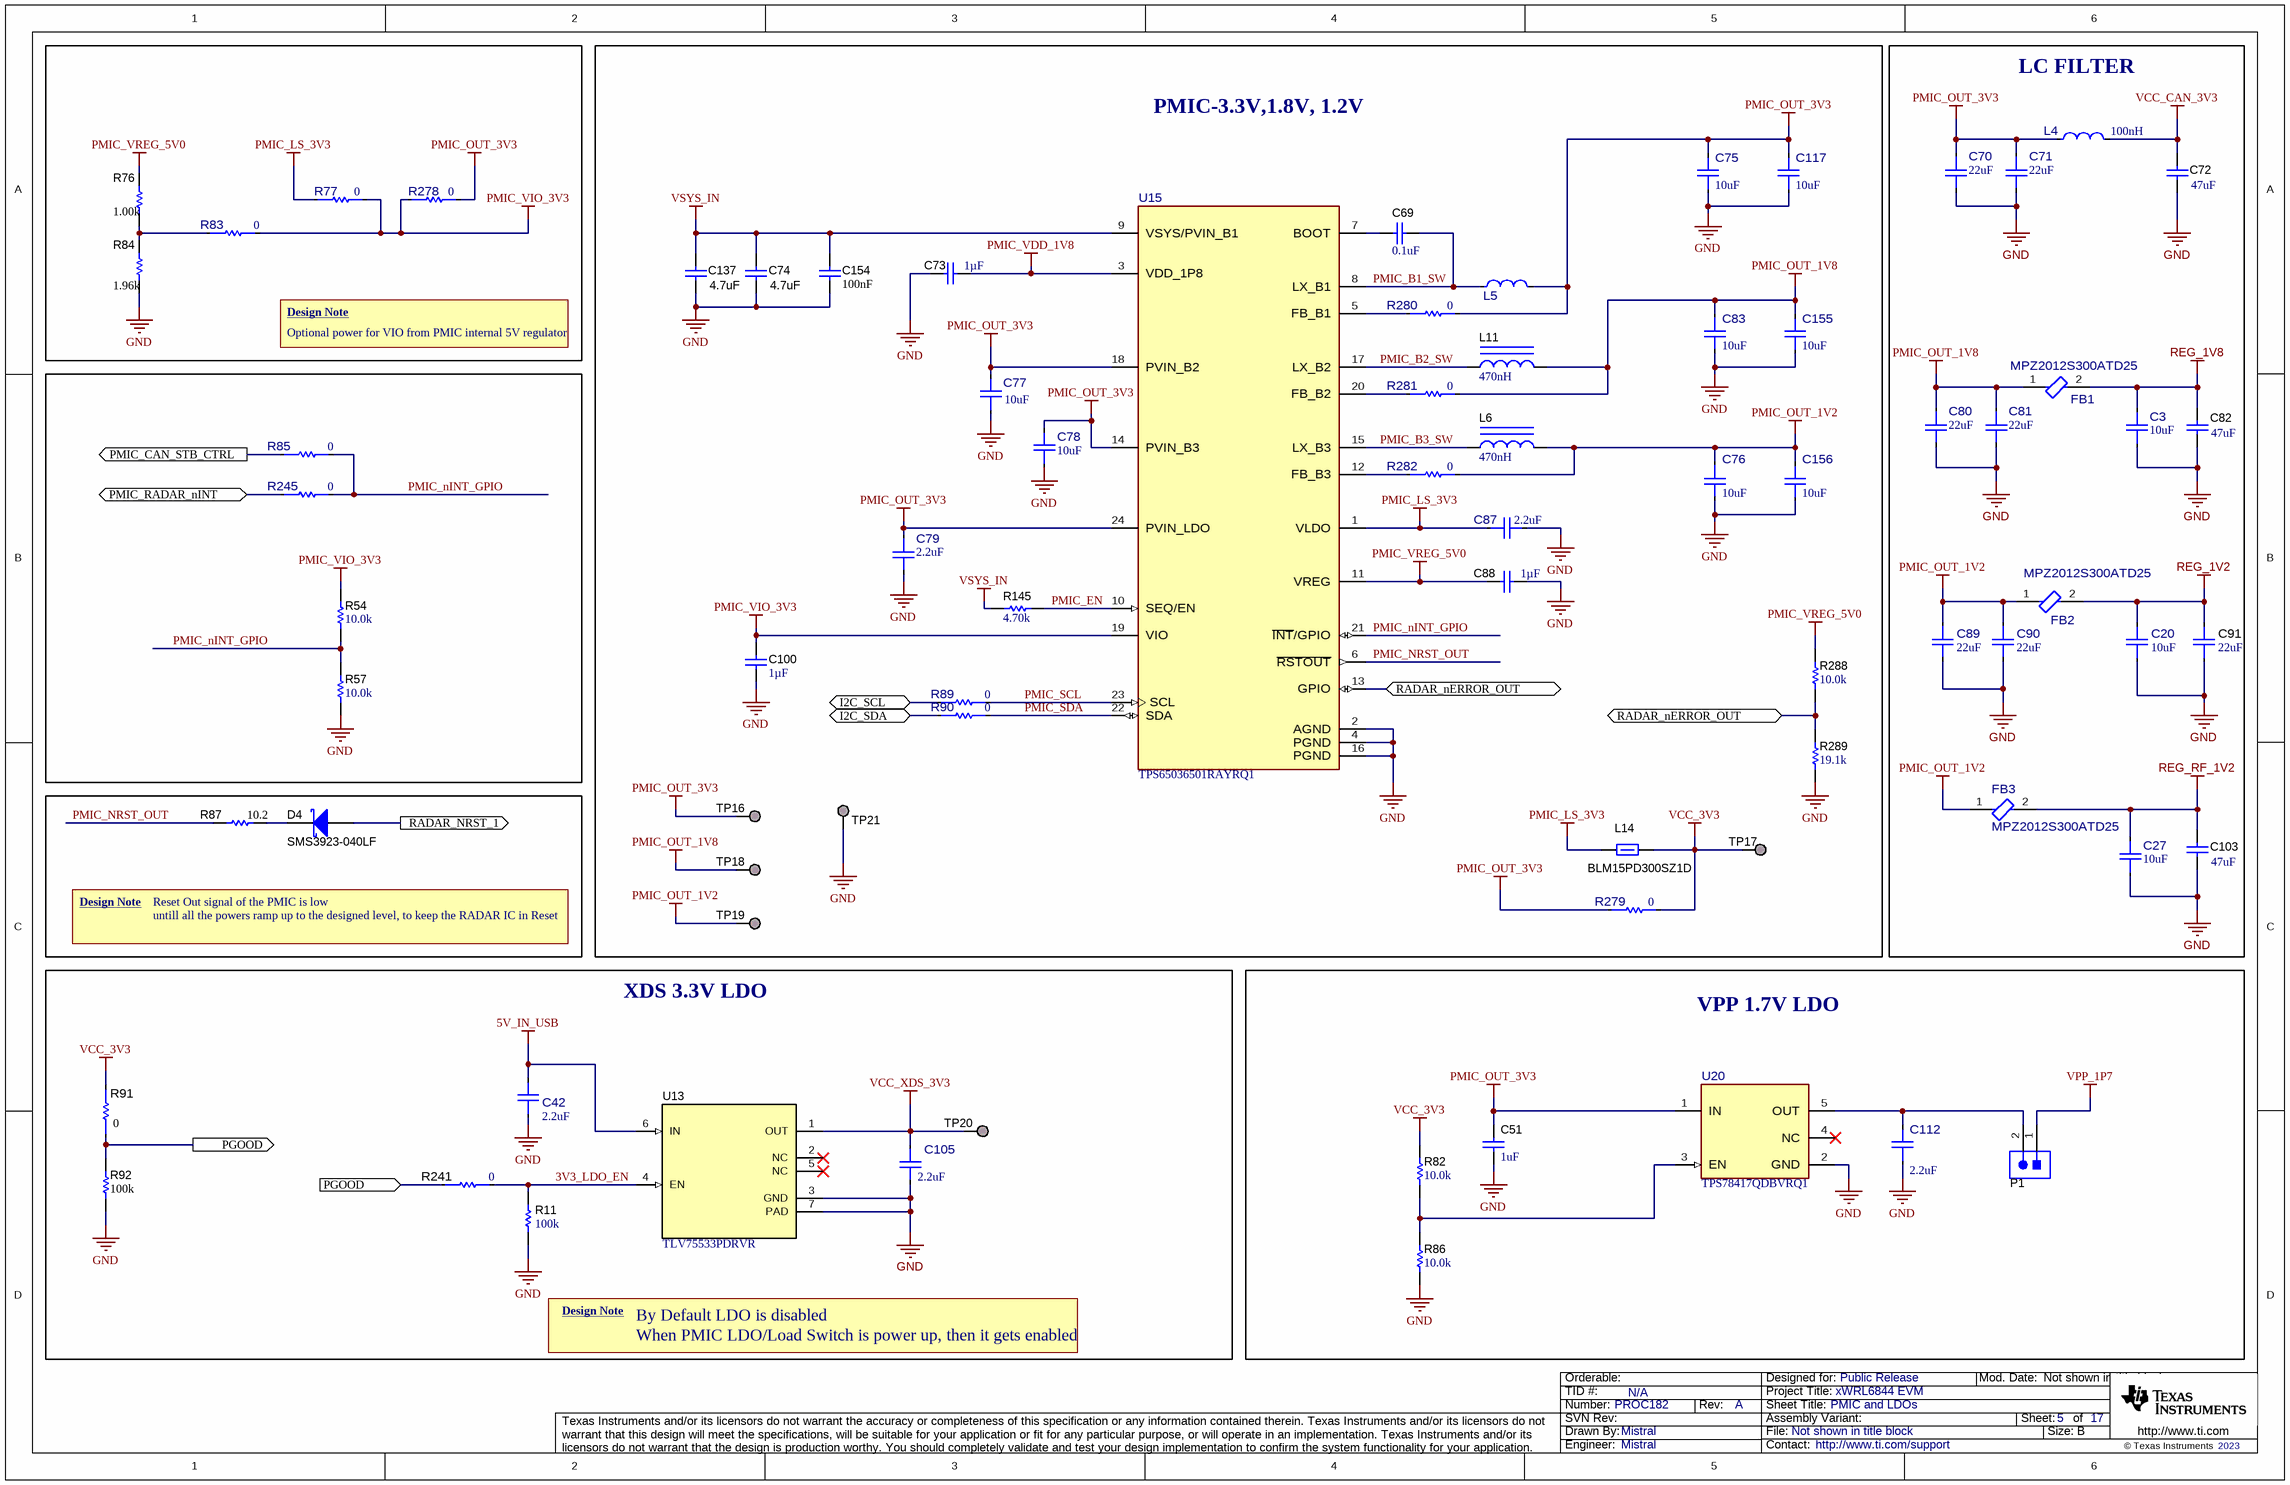
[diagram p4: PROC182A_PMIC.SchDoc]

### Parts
C3  ValueDisplayed: 10uF  [FP-CGA4J3X7S1A106K125AE_0805-MFG]  (hidden comment: CGA4J3X7S1A106K125AE)
C20  ValueDisplayed: 10uF  [FP-CGA4J3X7S1A106K125AE_0805-MFG]  (hidden comment: CGA4J3X7S1A106K125AE)
C27  ValueDisplayed: 10uF  [FP-CGA4J3X7S1A106K125AE_0805-MFG]  (hidden comment: CGA4J3X7S1A106K125AE)
C42  ValueDisplayed: 2.2uF  [FP-GRT155C71A225KE13D_0402-MFG]  (hidden comment: GRT155C71A225KE13D)
C51  ValueDisplayed: 1uF  [0402_070]  (hidden comment: GCM155C71A105KE38D)
C69  ValueDisplayed: 0.1uF  [0402]  (hidden comment: GCM155R71H104KE02D)
C70  ValueDisplayed: 22uF  [FP-GRM31CR70J226ME19K_1206-MFG]  (hidden comment: GRM31CR70J226ME19K)
C71  ValueDisplayed: 22uF  [FP-GRM31CR70J226ME19K_1206-MFG]  (hidden comment: GRM31CR70J226ME19K)
C72  ValueDisplayed: 47uF  [1206_180]  (hidden comment: GRM31CR60J476ME19L)
C73  Cap_F: 1µF  [0603]  (hidden comment: CL10B105KA8NNNC)
C74  ValueDisplayed: 4.7uF  [1206_180L]  (hidden comment: C3216X7R1H475K160AC)
C75  ValueDisplayed: 10uF  [FP-CGA4J3X7S1A106K125AE_0805-MFG]  (hidden comment: CGA4J3X7S1A106K125AE)
C76  ValueDisplayed: 10uF  [FP-CGA4J3X7S1A106K125AE_0805-MFG]  (hidden comment: CGA4J3X7S1A106K125AE)
C77  ValueDisplayed: 10uF  [FP-CGA4J3X7S1A106K125AE_0805-MFG]  (hidden comment: CGA4J3X7S1A106K125AE)
C78  ValueDisplayed: 10uF  [FP-CGA4J3X7S1A106K125AE_0805-MFG]  (hidden comment: CGA4J3X7S1A106K125AE)
C79  ValueDisplayed: 2.2uF  [FP-GRT155C71A225KE13D_0402-MFG]  (hidden comment: GRT155C71A225KE13D)
C80  ValueDisplayed: 22uF  [FP-GRM31CR70J226ME19K_1206-MFG]  (hidden comment: GRM31CR70J226ME19K)
C81  ValueDisplayed: 22uF  [FP-GRM31CR70J226ME19K_1206-MFG]  (hidden comment: GRM31CR70J226ME19K)
C82  ValueDisplayed: 47uF  [1206_180]  (hidden comment: GRM31CR60J476ME19L)
C83  ValueDisplayed: 10uF  [FP-CGA4J3X7S1A106K125AE_0805-MFG]  (hidden comment: CGA4J3X7S1A106K125AE)
C87  ValueDisplayed: 2.2uF  [FP-GRT155C71A225KE13D_0402-MFG]  (hidden comment: GRT155C71A225KE13D)
C88  Cap_F: 1µF  [0603]  (hidden comment: CL10B105KA8NNNC)
C89  ValueDisplayed: 22uF  [FP-GRM31CR70J226ME19K_1206-MFG]  (hidden comment: GRM31CR70J226ME19K)
C90  ValueDisplayed: 22uF  [FP-GRM31CR70J226ME19K_1206-MFG]  (hidden comment: GRM31CR70J226ME19K)
C91  ValueDisplayed: 22uF  [FP-GRM31CR70J226ME19K_1206-MFG]  (hidden comment: GRM31CR70J226ME19K)
C100  Cap_F: 1µF  [0603]  (hidden comment: CL10B105KA8NNNC)
C103  ValueDisplayed: 47uF  [1206_180]  (hidden comment: GRM31CR60J476ME19L)
C105  ValueDisplayed: 2.2uF  [FP-GRT155C71A225KE13D_0402-MFG]  (hidden comment: GRT155C71A225KE13D)
C112  ValueDisplayed: 2.2uF  [FP-GRT155C71A225KE13D_0402-MFG]  (hidden comment: GRT155C71A225KE13D)
C117  ValueDisplayed: 10uF  [FP-CGA4J3X7S1A106K125AE_0805-MFG]  (hidden comment: CGA4J3X7S1A106K125AE)
C137  ValueDisplayed: 4.7uF  [1206_180L]  (hidden comment: C3216X7R1H475K160AC)
C154  Cap_F: 100nF  [0402]  (hidden comment: GCM155R71H104KE02D)
C155  ValueDisplayed: 10uF  [FP-CGA4J3X7S1A106K125AE_0805-MFG]  (hidden comment: CGA4J3X7S1A106K125AE)
C156  ValueDisplayed: 10uF  [FP-CGA4J3X7S1A106K125AE_0805-MFG]  (hidden comment: CGA4J3X7S1A106K125AE)
D4  SMS3923-040LF  [SOD-882]
FB1  MPZ2012S300ATD25  [FP-MPZ2012S300ATD25_0805-MFG]
FB2  MPZ2012S300ATD25  [FP-MPZ2012S300ATD25_0805-MFG]
FB3  MPZ2012S300ATD25  [FP-MPZ2012S300ATD25_0805-MFG]
L4  Ind_H: 100nH  [FP-LQM2MPZR10MJHL_0806 (2016)-MFG]  (hidden comment: LQM2MPZR10MJHL)
L5  TFM252012ALVA1R5MTAA  [FP-TFM252012ALVA1R5MTAA_1008-MFG]  (value not drawn)
L6  ValueDisplayed: 470nH  [TFM201610ALMA]  (hidden comment: TFM201610ALMAR47MTAA)
L11  ValueDisplayed: 470nH  [TFM201610ALMA]  (hidden comment: TFM201610ALMAR47MTAA)
L14  BLM15PD300SZ1D  [0402L]
P1  TSW-102-07-G-S  [TSW-102-07-G-S]  (value not drawn)
R11  ValueDisplayed: 100k  [0402]  (hidden comment: CRCW0402100KFKED)
R54  ValueDisplayed: 10.0k  [0402L]  (hidden comment: CRCW040210K0FKED)
R57  ValueDisplayed: 10.0k  [0402L]  (hidden comment: CRCW040210K0FKED)
R76  ValueDisplayed: 1.00k  [0402]  (hidden comment: ERJ-2RKF1001X)
R77  value 0  [FP-ERJ-2GE0R00X_0402-MFG]  (hidden comment: ERJ-2GE0R00X)
R82  ValueDisplayed: 10.0k  [0402L]  (hidden comment: CRCW040210K0FKED)
R83  value 0  [FP-ERJ-2GE0R00X_0402-MFG]  (hidden comment: ERJ-2GE0R00X)
R84  ValueDisplayed: 1.96k  [0402]  (hidden comment: CRCW04021K96FKED)
R85  value 0  [FP-ERJ-2GE0R00X_0402-MFG]  (hidden comment: ERJ-2GE0R00X)
R86  ValueDisplayed: 10.0k  [0402L]  (hidden comment: CRCW040210K0FKED)
R87  ValueDisplayed: 10.2  [0402]  (hidden comment: CRCW040210R2FKED)
R89  value 0  [FP-ERJ-2GE0R00X_0402-MFG]  (hidden comment: ERJ-2GE0R00X)
R90  value 0  [FP-ERJ-2GE0R00X_0402-MFG]  (hidden comment: ERJ-2GE0R00X)
R91  value 0  [FP-ERJ-2GE0R00X_0402-MFG]  (hidden comment: ERJ-2GE0R00X)
R92  ValueDisplayed: 100k  [0402]  (hidden comment: CRCW0402100KFKED)
R145  value 4.70k  [0402]  (hidden comment: RC0402FR-074K7L)
R241  value 0  [FP-ERJ-2GE0R00X_0402-MFG]  (hidden comment: ERJ-2GE0R00X)
R245  value 0  [FP-ERJ-2GE0R00X_0402-MFG]  (hidden comment: ERJ-2GE0R00X)
R278  value 0  [FP-ERJ-2GE0R00X_0402-MFG]  (hidden comment: ERJ-2GE0R00X)
R279  value 0  [FP-ERJ-2GE0R00X_0402-MFG]  (hidden comment: ERJ-2GE0R00X)
R280  value 0  [FP-ERJ-2GE0R00X_0402-MFG]  (hidden comment: ERJ-2GE0R00X)
R281  value 0  [FP-ERJ-2GE0R00X_0402-MFG]  (hidden comment: ERJ-2GE0R00X)
R282  value 0  [FP-ERJ-2GE0R00X_0402-MFG]  (hidden comment: ERJ-2GE0R00X)
R288  ValueDisplayed: 10.0k  [0402L]  (hidden comment: CRCW040210K0FKED)
R289  ValueDisplayed: 19.1k  [0402]  (hidden comment: CRCW040219K1FKED)
TP16  TESTPOINT  [TP_25MIL-SMT]  (value not drawn)  (no BOM)
TP17  TESTPOINT  [TP_25MIL-SMT]  (value not drawn)  (no BOM)
TP18  TESTPOINT  [TP_25MIL-SMT]  (value not drawn)  (no BOM)
TP19  TESTPOINT  [TP_25MIL-SMT]  (value not drawn)  (no BOM)
TP20  TESTPOINT  [TP_25MIL-SMT]  (value not drawn)  (no BOM)
TP21  TESTPOINT  [TP_VIA_060RND040]  (value not drawn)  (no BOM)
U13  TLV75533PDRVR  [DRV0006A]
U15  TPS65036501RAYRQ1  [RAY0024B-MFG]
U20  TPS78417QDBVRQ1  [DBV0005A-MFG]

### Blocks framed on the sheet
PMIC-3.3V,1.8V, 1.2V: C69 C73-C79 C83 C87 C88 C100 C117 C137 C154-C156 L5 L6 L11 L14 R89 R90 R145 R279-R282 R288 R289 TP16-TP19 TP21 U15
LC FILTER: C3 C20 C27 C70-C72 C80-C82 C89-C91 C103 FB1-FB3 L4
VPP 1.7V LDO: C51 C112 P1 R82 R86 U20

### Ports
I2C_SCL (bidir), I2C_SDA (bidir), PGOOD (in), PGOOD (out), PMIC_CAN_STB_CTRL (out), PMIC_RADAR_nINT (bidir), RADAR_nERROR_OUT (bidir), RADAR_NRST_1 (out)

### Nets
5V_IN_USB: C42.2 U13.6(IN)
GND: C3.1 C20.1 C27.1 C42.1 C51.2 C70.2 C71.2 C72.1 C73.2 C74.2 C75.1 C76.2 C77.1 C78.1 C79.2 C80.2 C81.2 C82.1 C83.2 C87.2 C88.1 C89.2 C90.2 C91.1 C100.2 C103.1 C105.2 C112.1 C117.1 C137.2 C154.1 C155.1 C156.1 R11.1 R57.1 R84.1 R86.1 R92.1 R289.1 TP21.1 U13.3(GND) U13.7(PAD) U15.2(AGND) U15.4(PGND) U15.16(PGND) U20.2(GND)
PMIC_LS_3V3: C87.1 L14.1 R77.1 U15.1(VLDO)
PMIC_OUT_1V2: C76.1 C89.1 C90.1 C156.2 FB2.1 FB3.1 L6.2 R282.2 TP19.1
PMIC_OUT_1V8: C80.1 C81.1 C83.1 C155.2 FB1.1 L11.2 R281.2 TP18.1
PMIC_OUT_3V3: C51.1 C70.1 C71.1 C75.2 C77.2 C78.2 C79.1 C117.2 L4.1 L5.2 R278.2 R279.1 R280.2 TP16.1 U15.14(PVIN_B3) U15.18(PVIN_B2) U15.24(PVIN_LDO) U20.1(IN)
PMIC_VDD_1V8: C73.1 U15.3(VDD_1P8)
PMIC_VIO_3V3: C100.1 R54.2 R77.2 R83.2 R278.1 U15.19(VIO)
PMIC_VREG_5V0: C88.2 R76.1 R288.2 U15.11(VREG)
REG_1V2: C20.2 C91.2 FB2.2
REG_1V8: C3.2 C82.2 FB1.2
REG_RF_1V2: C27.2 C103.2 FB3.2
VCC_3V3: L14.2 R82.2 R91.2 R279.2 TP17.1
VCC_CAN_3V3: C72.2 L4.2
VCC_XDS_3V3: C105.1 TP20.1 U13.1(OUT)
VPP_1P7: P1.1
VSYS_IN: C74.1 C137.1 C154.2 R145.2 U15.9(VSYS/PVIN_B1)
3V3_LDO_EN: R11.2 R241.2 U13.4(EN)
I2C_SCL: R89.1 ; port I2C_SCL
I2C_SDA: R90.1 ; port I2C_SDA
PGOOD: R91.1 R92.2 R241.1 ; port PGOOD
PMIC_B1_SW: C69.2 L5.1 U15.8(LX_B1)
PMIC_B2_SW: L11.1 U15.17(LX_B2)
PMIC_B3_SW: L6.1 U15.15(LX_B3)
PMIC_CAN_STB_CTRL: R85.1 ; port PMIC_CAN_STB_CTRL
PMIC_EN: R145.1 U15.10(SEQ/EN)
PMIC_nINT_GPIO: R54.1 R57.2 R85.2 R245.2 U15.21(~{INT}/GPIO)
PMIC_NRST_OUT: R87.1 U15.6(~{RSTOUT})
PMIC_RADAR_nINT: R245.1 ; port PMIC_RADAR_nINT
PMIC_SCL: R89.2 U15.23(SCL)
PMIC_SDA: R90.2 U15.22(SDA)
RADAR_nERROR_OUT: R288.1 R289.2 U15.13(GPIO) ; port RADAR_nERROR_OUT
RADAR_NRST_1: D4.2(A) ; port RADAR_NRST_1
NetC69_1: C69.1 U15.7(BOOT)
NetC112_2: C112.2 P1.2 U20.5(OUT)
NetD4_1: D4.1(K) R87.2
NetR76_2: R76.2 R83.1 R84.2
NetR82_1: R82.1 R86.2 U20.3(EN)
NetR280_1: R280.1 U15.5(FB_B1)
NetR281_1: R281.1 U15.20(FB_B2)
NetR282_1: R282.1 U15.12(FB_B3)

Not connected (* = marked no-connect by the designer): U13 2(NC)* 5(NC)*; U20 4(NC)*

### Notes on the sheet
- Design Note
- Optional power for VIO from PMIC internal 5V regulator
- Reset Out signal of the PMIC is low
- untill all the powers ramp up to the designed level, to keep the RADAR IC in Reset
- XDS 3.3V LDO
- By Default LDO is disabled
- When PMIC LDO/Load Switch is power up, then it gets enabled

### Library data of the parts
C3 C20 C27 C75-C78 C83 C117 C155 C156 = CMP-0089543-1: 10µF ±10% 10V Ceramic Capacitor X7S 0805 (2012 Metric); Manufacturer: TDK; TempCo: 22%; SizeZ_mm: 1.5mm; AEC Qualified: Yes; AEC Grade: Grade 1
C42 C79 C87 C105 = CMP-0094968-1: Multi-Layer Ceramic Capacitor 2.2uF 10V X7S ±10% 0402 Paper T/R; Manufacturer: Murata; TempCo: 22%; Value: 2.2µF; SizeZ_mm: 0.7mm; AEC Qualified: Yes; AEC Grade: Grade 1
C51 = CMP-0006349-2: as C66 on sheet PROC182A_USB_PWR_DC_Jack_Switch
C69 = CMP-0006356-2: as C48 on sheet PROC182A_USB_PWR_DC_Jack_Switch
C70 C71 C80 C81 C89 C90 = CMP-0092150-1: Chip Multilayer Ceramic Capacitors for General Purpose, 1206, 22uF, X7R, 15%, 20%, 6.3V; Manufacturer: Murata; Value: 22µF; SizeZ_mm: 1.8mm; AEC Qualified: No
C72 C82 C103 = CMP-0008940-2: CAP, CERM, 47 uF, 6.3 V, +/- 20%, X5R, 1206; Manufacturer: MuRata; TaMin_C: -55°C; ESR_ohm: 3m; Polarized: N; SizeAreaWB_mm2: 10.92; Value1: 0.003 ohm; U/M: EA; Value: 47uF; TaMax_C: 85°C; SizeZ_mm: 1.8; SizeX_mm: 3.2; SizeY_mm: 1.6; Cap_Case: 1206; Value2: 6.3V; SizeArea_mm2: 5.12; Cap_F: 47µF; AEC Category: Q200
C73 C88 C100 = CMP-0086540-3: as C54 on sheet PROC182A_USB_PWR_DC_Jack_Switch
C74 C137 = CMP-0008702-2: as C43 on sheet PROC182A_USB_PWR_DC_Jack_Switch
C91 = CMP-0092150-1: Chip Multilayer Ceramic Capacitors for General Purpose, 1206, 22uF, X7R, 15%, 20%, 6.3V; Manufacturer: Murata; SizeZ_mm: 1.8mm; AEC Qualified: No; Value: 22µF
C112 = CMP-0094968-1: Multi-Layer Ceramic Capacitor 2.2uF 10V X7S ±10% 0402 Paper T/R; Manufacturer: Murata; AEC Grade: Grade 1; Cap_F: 2.2µF; SizeZ_mm: 0.7mm; Value: 2.2µF; AEC Qualified: Yes; TempCo: 22%
C154 = CMP-0006356-2: as C60 on sheet PROC182A_USB_PWR_DC_Jack_Switch
D4 = CMP-0078187-3: Diode, Schottky,  V, 0.01 A, SOD-882; Manufacturer: Skyworks Solutions; SizeArea_mm2: 0.6; SizeAreaWB_mm2: 3.2; Io_A: 10mA; SizeX_mm: 1; Value1: 0.01A; SizeZ_mm: 0.5; Value2: 0.34V; AEC Category: Q101; Vf_V: 340mV; TJmax_C: 150°C; AEC Qualified: N
FB1-FB3 = CMP-0091544-1: 30 Ohms @ 100MHz 1 Power Line Ferrite Bead 0805 (2012 Metric) 6A 10mOhm; Manufacturer: TDK; AEC Grade: Grade 1; Impedance At Frequency: 30Ω @ 100MHz; SizeZ_mm: 1.05mm; DCR_ohm: 10m; AEC Qualified: Yes
L4 = CMP-0095018-1: 100nH Shielded Multilayer Inductor 4A 19mOhm Max 0806 (2016 Metric); Manufacturer: Murata; Tolerance_%: 20%; Self Resonant Frequency: 200MHz; Test Frequency: 1MHz; Irms: 4000mA; Shrouded: true; SizeZ_mm: 1.2mm; Value: 0.1uH; AEC Grade: Grade 1; DCR_ohm: 0.019; Material: Ferrite; AEC Qualified: Yes
L5 = CMP-0121156-1: 1.5 µH Shielded Thin Film Inductor 3.1 A 60mOhm Max 1008 (2520 Metric); Manufacturer: TDK; AEC Grade: Grade 0; AEC Qualified: Yes; DCR_ohm: 60m; Ind_H: 1.5µH; Irms: 3.3A; Material: Metal; SizeZ_mm: 1.2mm; Value: 1.5uH; Shrouded: true; Test Frequency: 1MHz; Tolerance_%: 20%
L6 L11 = CMP-0081095-1: Inductor, Shielded, Metal Composite, 470 nH, 3.9 A, 0.039 ohm, AEC-Q200 Grade 0, SMD; Manufacturer: TDK; Isat: 4.5A @ 30% inductance drop; Irms: 3.9A @ 40C rise; SizeAreaWB_mm2: 7.8; DCR_ohm: 39m; Value: 470nH; Imax_A: 3.9A; SizeZ_mm: 1; SizeX_mm: 2; SizeY_mm: 1.6; SizeArea_mm2: 3.2; AEC Qualified: Y; AEC Grade: 0; AEC Category: Q200
L14 = CMP-0078934-1: Inductor, Ferrite Bead, Ferrite, 2.2 A, 0.035 ohm, AEC-Q200 Grade 1, SMD; Manufacturer: MuRata; AEC Category: Q200; AEC Grade: 1; AEC Qualified: Y; DCR_ohm: 0.035; Imax_A: 2.2A; SizeArea_mm2: 0.5; SizeAreaWB_mm2: 3; SizeZ_mm: 0.6
P1 = CMP-0075405-3: Header, 100mil, 2x1, Gold, TH; Manufacturer: Samtec; Pitch_mm: 2.54; Cert_VDE: N; Gender: Male; Cert_CSA: Y; Voltage_V: 550V; Green_REACh: Passed; Current_A: 6.3A; Green_Lifecycle: Active; Row_Count: 1
R11 R92 = CMP-0025950-3: RES, 100 k, 1%, 0.063 W, AEC-Q200 Grade 0, 0402; Manufacturer: Vishay-Dale; Power_W: 63mW; TempCo: 100 ppm/C; Value: 100k; EIA_Code: E96; SizeX_mm: 1; SizeY_mm: 0.5; SizeZ_mm: 0.6; Value2: 0.063W; AEC Qualified: Y; VDC_V: 50V; AEC Category: Q200; AEC Grade: 0
R54 R57 R82 R86 R288 = CMP-0025958-3: as R9 on sheet PROC182A_USB_PWR_DC_Jack_Switch
R76 = CMP-0026657-1: as R174 on sheet PROC182A_USB_PWR_DC_Jack_Switch
R77 R83 R278-R282 = CMP-0002710-1: 0 Ohms Jumper Chip Resistor 0402 (1005 Metric) Automotive AEC-Q200 Thick Film; Manufacturer: Panasonic; AEC Grade: Grade 0; AEC Qualified: Yes; SizeZ_mm: 0.4mm; Power: 100mW
R84 = CMP-0026099-2: RES, 1.96 k, 1%, 0.063 W, AEC-Q200 Grade 0, 0402; Manufacturer: Vishay-Dale; Power_W: 63mW; TempCo: 100 ppm/C; Value_Code: 1k96; Value: 1.96k; EIA_Code: E96; SizeX_mm: 1; SizeY_mm: 0.5; SizeZ_mm: 0.6; Value2: 0.063W; AEC Qualified: Y; VDC_V: 50V; AEC Category: Q200; AEC Grade: 0
R85 R89-R91 R241 R245 = CMP-0002710-1: 0 Ohms Jumper Chip Resistor 0402 (1005 Metric) Automotive AEC-Q200 Thick Film; Manufacturer: Panasonic; SizeZ_mm: 0.4mm; AEC Qualified: Yes; AEC Grade: Grade 0; Power: 100mW
R87 = CMP-0025964-3: RES, 10.2, 1%, 0.063 W, AEC-Q200 Grade 0, 0402; Manufacturer: Vishay-Dale; Power_W: 63mW; TempCo: 100 ppm/C; Value_Code: 10R2; Value: 10.2; EIA_Code: E96; SizeX_mm: 1; SizeY_mm: 0.5; SizeZ_mm: 0.6; Value2: 0.063W; AEC Qualified: Y; VDC_V: 50V; AEC Category: Q200; AEC Grade: 0
R145 = CMP-0026739-1: RES, 4.70 k, 1%, 0.0625 W, 0402; Manufacturer: Yageo America; VDC_V: 50V; AEC Qualified: N; SizeZ_mm: 0.6; TempCo: 100 ppm/C; AEC Category: Q200; Power_W: 62.5mW; Res_ohm: 4.7k; SizeArea_mm2: 0.5; SizeX_mm: 1; U/M: EA; Value_Code: 4k70
R289 = CMP-0026067-3: RES, 19.1 k, 1%, 0.063 W, AEC-Q200 Grade 0, 0402; Manufacturer: Vishay-Dale; Power_W: 63mW; TempCo: 100 ppm/C; Value_Code: 19k1; Value: 19.1k; EIA_Code: E96; SizeX_mm: 1; SizeY_mm: 0.5; SizeZ_mm: 0.6; Value2: 0.063W; AEC Qualified: Y; VDC_V: 50V; AEC Category: Q200; AEC Grade: 0
TP16-TP21 = CMP-0078143-3: TEST POINT.  No entry in BOM.
U13 = CMP-0013427-7: 500mA LDO, DRV0006A (WSON-6); Manufacturer: Texas Instruments; SizeX_mm: 2; CompType: IC; SizeZ_mm: 0.8; SizeArea_mm2: 4; SizeAreaWB_mm2: 9; U/M: EA
U15 = CMP-0123008-1: Automotive Camera, Radar and MCU PMIC; Manufacturer: Texas Instruments; SizeZ_mm: 1mm; AEC Qualified: No; Max Supply Voltage: 35V; Min Supply Voltage: 4V; Number Of Outputs: 4; Output Voltage: 3-5.5V; Standoff Height: 0mm; TaMax_C: +125°C; TaMin_C: -40°C
U20 = CMP-0092338-1: Linear Voltage Regulator IC Positive Fixed Output 300mA SOT-23-5; Manufacturer: Texas Instruments; TaMin_C: -40°C; Output Voltage: 1.7V; Standoff Height: 0mm; SizeZ_mm: 1.45mm; TaMax_C: +125°C; Accuracy Percentage: 0.5%; AEC Grade: Grade 1; Number Of Outputs: 1; AEC Qualified: Yes; Max Supply Voltage: 6V; Dropout Voltage: 900mV; Nominal Supply Current: 0.033mA; Min Supply Voltage: 1.65V; TJmax_C: +150°C

## Sheet PROC182A_Chip.SchDoc: xWRL6844_CHIP
size 431 x 279 mm; Date: Not shown in title block; ApprovedBy: Not shown in title block; CheckedBy: Not shown in title block; Author: Not shown in title block; CompanyName: Not shown in title block; DrawnBy: Mistral; Engineer: Not shown in title block; Organization: Not shown in title block; Address1: Not shown in title block; Address2: Not shown in title block; Address3: Not shown in title block; Address4: Not shown in title block; DocumentNumber: 1; Revision: Use project parameter SCH_Rev; SheetNumber: 6; SheetTotal: 17; PageSetup: Record=PageOptions¦CenterHorizontal=True¦CenterVertical=True¦PrintScale=1.00¦XCorrection=1.00¦YCorrection=1.00¦PrintKind=0¦BorderSize=5000000¦LeftOffset=0¦BottomOffset=0¦Orientation=2¦PaperLength=1000¦PaperWidth=1000¦Scale=100¦PaperSource=15¦PrintQuality=600¦MediaType=1¦DitherType=10¦PaperKind=Letter¦PrintScaleMode=1
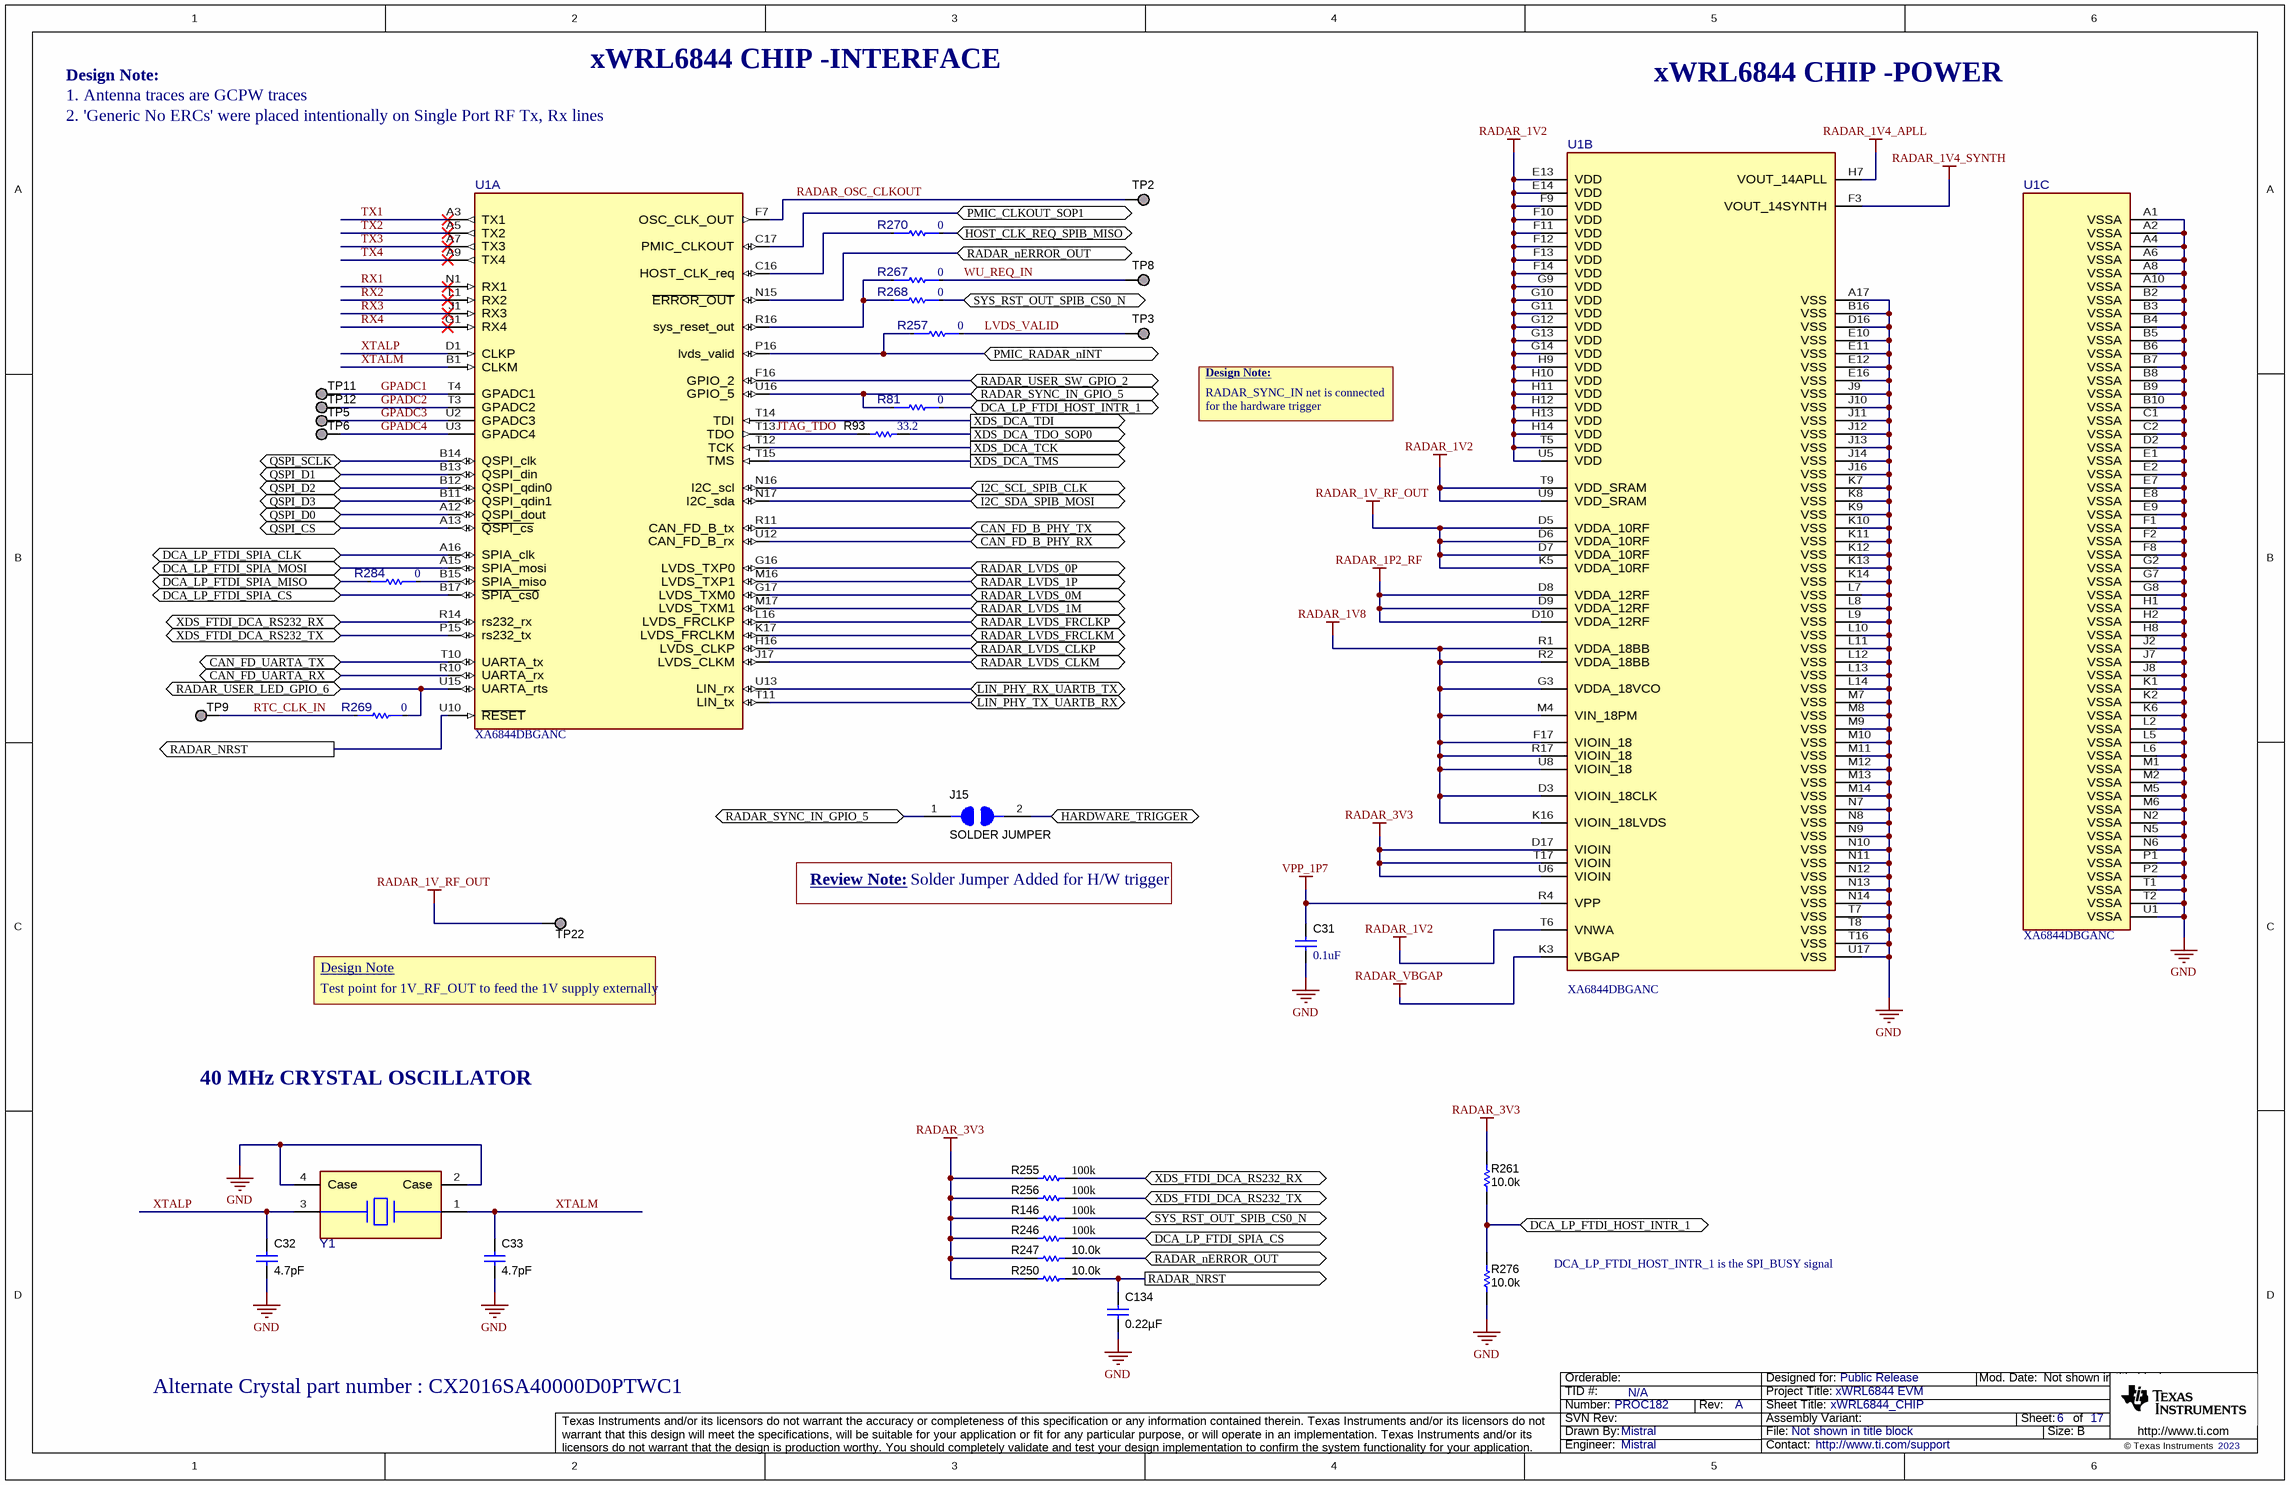
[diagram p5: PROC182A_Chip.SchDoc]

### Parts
C31  ValueDisplayed: 0.1uF  [0402]  (hidden comment: GCM155R71H104KE02D)
C32  ValueDisplayed: 4.7pF  [0402L]  (hidden comment: GJM1555C1H4R7BB01D)
C33  ValueDisplayed: 4.7pF  [0402L]  (hidden comment: GJM1555C1H4R7BB01D)
C134  ValueDisplayed: 0.22µF  [0402L]  (hidden comment: GCM155R71C224KE02D)
J15  SOLDER JUMPER  [SolderJumper]
R81  value 0  [FP-ERJ-2GE0R00X_0402-MFG]  (hidden comment: ERJ-2GE0R00X)
R93  value 33.2  [0402]  (hidden comment: CRCW040233R2FKED)
R146  value 100k  [0402L]  (hidden comment: CRCW0402100KFKED)
R246  value 100k  [0402L]  (hidden comment: CRCW0402100KFKED)
R247  ValueDisplayed: 10.0k  [0402L]  (hidden comment: CRCW040210K0FKED)
R250  ValueDisplayed: 10.0k  [0402L]  (hidden comment: CRCW040210K0FKED)
R255  ValueDisplayed: 100k  [0402L]  (hidden comment: CRCW0402100KFKED)
R256  ValueDisplayed: 100k  [0402L]  (hidden comment: CRCW0402100KFKED)
R257  value 0  [FP-ERJ-2GE0R00X_0402-MFG]  (hidden comment: ERJ-2GE0R00X)
R261  ValueDisplayed: 10.0k  [0402L]  (hidden comment: CRCW040210K0FKED)
R267  value 0  [FP-ERJ-2GE0R00X_0402-MFG]  (hidden comment: ERJ-2GE0R00X)
R268  value 0  [FP-ERJ-2GE0R00X_0402-MFG]  (hidden comment: ERJ-2GE0R00X)
R269  value 0  [FP-ERJ-2GE0R00X_0402-MFG]  (hidden comment: ERJ-2GE0R00X)
R270  value 0  [FP-ERJ-2GE0R00X_0402-MFG]  (hidden comment: ERJ-2GE0R00X)
R276  ValueDisplayed: 10.0k  [0402L]  (hidden comment: CRCW040210K0FKED)
R284  value 0  [FP-ERJ-2GE0R00X_0402-MFG]  (hidden comment: ERJ-2GE0R00X)
TP2  TESTPOINT  [TP_25MIL-SMT]  (value not drawn)  (no BOM)
TP3  TESTPOINT  [TP_25MIL-SMT]  (value not drawn)  (no BOM)
TP5  TESTPOINT  [TP_25MIL-SMT]  (value not drawn)  (no BOM)
TP6  TESTPOINT  [TP_25MIL-SMT]  (value not drawn)  (no BOM)
TP8  TESTPOINT  [TP_25MIL-SMT]  (value not drawn)  (no BOM)
TP9  TESTPOINT  [TP_25MIL-SMT]  (value not drawn)  (no BOM)
TP11  TESTPOINT  [TP_25MIL-SMT]  (value not drawn)  (no BOM)
TP12  TESTPOINT  [TP_25MIL-SMT]  (value not drawn)  (no BOM)
TP22  TESTPOINT  [TP_VIA_060RND040]  (value not drawn)  (no BOM)
U1  XA6844DBGANC  [ANC0207A-MFG]  (parts A,B,C of 3)
Y1  FW4000044Q  [FP-FW4000044Q_4-SMD-2.0x1.6mm-MFG]  (value not drawn)

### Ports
CAN_FD_B_PHY_RX (bidir), CAN_FD_B_PHY_TX (bidir), CAN_FD_UARTA_RX (bidir), CAN_FD_UARTA_TX (bidir), DCA_LP_FTDI_HOST_INTR_1 (bidir), DCA_LP_FTDI_SPIA_CLK (bidir), DCA_LP_FTDI_SPIA_CS (bidir), DCA_LP_FTDI_SPIA_MISO (bidir), DCA_LP_FTDI_SPIA_MOSI (bidir), HARDWARE_TRIGGER (bidir), HOST_CLK_REQ_SPIB_MISO (bidir), I2C_SCL_SPIB_CLK (bidir), I2C_SDA_SPIB_MOSI (bidir), LIN_PHY_RX_UARTB_TX (bidir), LIN_PHY_TX_UARTB_RX (bidir), PMIC_CLKOUT_SOP1 (bidir), PMIC_RADAR_nINT (bidir), QSPI_CS (bidir), QSPI_D0 (bidir), QSPI_D1 (bidir), QSPI_D2 (bidir), QSPI_D3 (bidir), QSPI_SCLK (bidir), RADAR_LVDS_0M (bidir), RADAR_LVDS_0P (bidir), RADAR_LVDS_1M (bidir), RADAR_LVDS_1P (bidir), RADAR_LVDS_CLKM (bidir), RADAR_LVDS_CLKP (bidir), RADAR_LVDS_FRCLKM (bidir), RADAR_LVDS_FRCLKP (bidir), RADAR_nERROR_OUT (bidir), RADAR_NRST (out), RADAR_SYNC_IN_GPIO_5 (bidir), RADAR_USER_LED_GPIO_6 (bidir), RADAR_USER_SW_GPIO_2 (bidir), SYS_RST_OUT_SPIB_CS0_N (bidir), XDS_DCA_TCK (out), XDS_DCA_TDI (out), XDS_DCA_TDO_SOP0 (out), XDS_DCA_TMS (out), XDS_FTDI_DCA_RS232_RX (bidir), XDS_FTDI_DCA_RS232_TX (bidir)

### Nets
GND: C31.2 C32.1 C33.1 C134.1 R276.2 U1.A1(VSSA) U1.A2(VSSA) U1.A4(VSSA) U1.A6(VSSA) U1.A8(VSSA) U1.A10(VSSA) U1.A17(VSS) U1.B2(VSSA) U1.B3(VSSA) U1.B4(VSSA) U1.B5(VSSA) U1.B6(VSSA) U1.B7(VSSA) U1.B8(VSSA) U1.B9(VSSA) U1.B10(VSSA) U1.B16(VSS) U1.C1(VSSA) U1.C2(VSSA) U1.D2(VSSA) U1.D16(VSS) U1.E1(VSSA) U1.E2(VSSA) U1.E7(VSSA) U1.E8(VSSA) U1.E9(VSSA) U1.E10(VSS) U1.E11(VSS) U1.E12(VSS) U1.E16(VSS) U1.F1(VSSA) U1.F2(VSSA) U1.F8(VSSA) U1.G2(VSSA) U1.G7(VSSA) U1.G8(VSSA) U1.H1(VSSA) U1.H2(VSSA) U1.H8(VSSA) U1.J2(VSSA) U1.J7(VSSA) U1.J8(VSSA) U1.J9(VSS) U1.J10(VSS) U1.J11(VSS) U1.J12(VSS) U1.J13(VSS) U1.J14(VSS) U1.J16(VSS) U1.K1(VSSA) U1.K2(VSSA) U1.K6(VSSA) U1.K7(VSS) U1.K8(VSS) U1.K9(VSS) U1.K10(VSS) U1.K11(VSS) U1.K12(VSS) U1.K13(VSS) U1.K14(VSS) U1.L2(VSSA) U1.L5(VSSA) U1.L6(VSSA) U1.L7(VSS) U1.L8(VSS) U1.L9(VSS) U1.L10(VSS) U1.L11(VSS) U1.L12(VSS) U1.L13(VSS) U1.L14(VSS) U1.M1(VSSA) U1.M2(VSSA) U1.M5(VSSA) U1.M6(VSSA) U1.M7(VSS) U1.M8(VSS) U1.M9(VSS) U1.M10(VSS) U1.M11(VSS) U1.M12(VSS) U1.M13(VSS) U1.M14(VSS) U1.N2(VSSA) U1.N5(VSSA) U1.N6(VSSA) U1.N7(VSS) U1.N8(VSS) U1.N9(VSS) U1.N10(VSS) U1.N11(VSS) U1.N12(VSS) U1.N13(VSS) U1.N14(VSS) U1.P1(VSSA) U1.P2(VSSA) U1.T1(VSSA) U1.T2(VSSA) U1.T7(VSS) U1.T8(VSS) U1.T16(VSS) U1.U1(VSSA) U1.U17(VSS) Y1.2(Case) Y1.4(Case)
RADAR_1P2_RF: U1.D8(VDDA_12RF) U1.D9(VDDA_12RF) U1.D10(VDDA_12RF)
RADAR_1V2: U1.E13(VDD) U1.E14(VDD) U1.F9(VDD) U1.F10(VDD) U1.F11(VDD) U1.F12(VDD) U1.F13(VDD) U1.F14(VDD) U1.G9(VDD) U1.G10(VDD) U1.G11(VDD) U1.G12(VDD) U1.G13(VDD) U1.G14(VDD) U1.H9(VDD) U1.H10(VDD) U1.H11(VDD) U1.H12(VDD) U1.H13(VDD) U1.H14(VDD) U1.T5(VDD) U1.T6(VNWA) U1.T9(VDD_SRAM) U1.U5(VDD) U1.U9(VDD_SRAM)
RADAR_1V4_APLL: U1.H7(VOUT_14APLL)
RADAR_1V4_SYNTH: U1.F3(VOUT_14SYNTH)
RADAR_1V8: U1.D3(VIOIN_18CLK) U1.F17(VIOIN_18) U1.G3(VDDA_18VCO) U1.K16(VIOIN_18LVDS) U1.M4(VIN_18PM) U1.R1(VDDA_18BB) U1.R2(VDDA_18BB) U1.R17(VIOIN_18) U1.U8(VIOIN_18)
RADAR_1V_RF_OUT: TP22.1 U1.D5(VDDA_10RF) U1.D6(VDDA_10RF) U1.D7(VDDA_10RF) U1.K5(VDDA_10RF)
RADAR_3V3: R146.2 R246.2 R247.2 R250.2 R255.2 R256.2 R261.1 U1.D17(VIOIN) U1.T17(VIOIN) U1.U6(VIOIN)
RADAR_VBGAP: U1.K3(VBGAP)
VPP_1P7: C31.1 U1.R4(VPP)
CAN_FD_B_PHY_RX: U1.U12(CAN_FD_B_rx) ; port CAN_FD_B_PHY_RX
CAN_FD_B_PHY_TX: U1.R11(CAN_FD_B_tx) ; port CAN_FD_B_PHY_TX
CAN_FD_UARTA_RX: U1.R10(UARTA_rx) ; port CAN_FD_UARTA_RX
CAN_FD_UARTA_TX: U1.T10(UARTA_tx) ; port CAN_FD_UARTA_TX
DCA_LP_FTDI_HOST_INTR_1: R81.2 R261.2 R276.1 ; port DCA_LP_FTDI_HOST_INTR_1
DCA_LP_FTDI_SPIA_CLK: U1.A16(SPIA_clk) ; port DCA_LP_FTDI_SPIA_CLK
DCA_LP_FTDI_SPIA_CS: R246.1 U1.B17(~{SPIA_cs0}) ; port DCA_LP_FTDI_SPIA_CS
DCA_LP_FTDI_SPIA_MISO: R284.1 ; port DCA_LP_FTDI_SPIA_MISO
DCA_LP_FTDI_SPIA_MOSI: U1.A15(SPIA_mosi) ; port DCA_LP_FTDI_SPIA_MOSI
GPADC1: TP11.1 U1.T4(GPADC1)
GPADC2: TP12.1 U1.T3(GPADC2)
GPADC3: TP5.1 U1.U2(GPADC3)
GPADC4: TP6.1 U1.U3(GPADC4)
HARDWARE_TRIGGER: J15.2 ; port HARDWARE_TRIGGER
HOST_CLK_REQ_SPIB_MISO: R270.2 ; port HOST_CLK_REQ_SPIB_MISO
I2C_SCL_SPIB_CLK: U1.N16(I2C_scl) ; port I2C_SCL_SPIB_CLK
I2C_SDA_SPIB_MOSI: U1.N17(I2C_sda) ; port I2C_SDA_SPIB_MOSI
JTAG_TDO: R93.2 U1.T13(TDO)
LIN_PHY_RX_UARTB_TX: U1.U13(LIN_rx) ; port LIN_PHY_RX_UARTB_TX
LIN_PHY_TX_UARTB_RX: U1.T11(LIN_tx) ; port LIN_PHY_TX_UARTB_RX
LVDS_VALID: R257.2 TP3.1
PMIC_CLKOUT_SOP1: U1.C17(PMIC_CLKOUT) ; port PMIC_CLKOUT_SOP1
PMIC_RADAR_nINT: R257.1 U1.P16(lvds_valid) ; port PMIC_RADAR_nINT
QSPI_CS: U1.A13(~{QSPI_cs}) ; port QSPI_CS
QSPI_D0: U1.A12(QSPI_dout) ; port QSPI_D0
QSPI_D1: U1.B13(QSPI_din) ; port QSPI_D1
QSPI_D2: U1.B12(QSPI_qdin0) ; port QSPI_D2
QSPI_D3: U1.B11(QSPI_qdin1) ; port QSPI_D3
QSPI_SCLK: U1.B14(QSPI_clk) ; port QSPI_SCLK
RADAR_LVDS_0M: U1.G17(LVDS_TXM0) ; port RADAR_LVDS_0M
RADAR_LVDS_0P: U1.G16(LVDS_TXP0) ; port RADAR_LVDS_0P
RADAR_LVDS_1M: U1.M17(LVDS_TXM1) ; port RADAR_LVDS_1M
RADAR_LVDS_1P: U1.M16(LVDS_TXP1) ; port RADAR_LVDS_1P
RADAR_LVDS_CLKM: U1.J17(LVDS_CLKM) ; port RADAR_LVDS_CLKM
RADAR_LVDS_CLKP: U1.H16(LVDS_CLKP) ; port RADAR_LVDS_CLKP
RADAR_LVDS_FRCLKM: U1.K17(LVDS_FRCLKM) ; port RADAR_LVDS_FRCLKM
RADAR_LVDS_FRCLKP: U1.L16(LVDS_FRCLKP) ; port RADAR_LVDS_FRCLKP
RADAR_nERROR_OUT: R247.1 U1.N15(~{ERROR_OUT}) ; port RADAR_nERROR_OUT
RADAR_NRST: C134.2 R250.1 U1.U10(~{RESET}) ; port RADAR_NRST
RADAR_OSC_CLKOUT: TP2.1 U1.F7(OSC_CLK_OUT)
RADAR_SYNC_IN_GPIO_5: J15.1 R81.1 U1.U16(GPIO_5) ; port RADAR_SYNC_IN_GPIO_5
RADAR_USER_LED_GPIO_6: R269.2 U1.U15(UARTA_rts) ; port RADAR_USER_LED_GPIO_6
RADAR_USER_SW_GPIO_2: U1.F16(GPIO_2) ; port RADAR_USER_SW_GPIO_2
RTC_CLK_IN: R269.1 TP9.1
RX1: U1.N1(RX1)
RX2: U1.L1(RX2)
RX3: U1.J1(RX3)
RX4: U1.G1(RX4)
SYS_RST_OUT_SPIB_CS0_N: R146.1 R268.2 ; port SYS_RST_OUT_SPIB_CS0_N
TX1: U1.A3(TX1)
TX2: U1.A5(TX2)
TX3: U1.A7(TX3)
TX4: U1.A9(TX4)
WU_REQ_IN: R267.2 TP8.1
XDS_DCA_TCK: U1.T12(TCK) ; port XDS_DCA_TCK
XDS_DCA_TDI: U1.T14(TDI) ; port XDS_DCA_TDI
XDS_DCA_TDO_SOP0: R93.1 ; port XDS_DCA_TDO_SOP0
XDS_DCA_TMS: U1.T15(TMS) ; port XDS_DCA_TMS
XDS_FTDI_DCA_RS232_RX: R255.1 U1.R14(rs232_rx) ; port XDS_FTDI_DCA_RS232_RX
XDS_FTDI_DCA_RS232_TX: R256.1 U1.P15(rs232_tx) ; port XDS_FTDI_DCA_RS232_TX
XTALM: C33.2 U1.B1(CLKM) Y1.1(1_Xtal)
XTALP: C32.2 U1.D1(CLKP) Y1.3(2_Xtal)
NetR267_1: R267.1 R268.1 U1.R16(sys_reset_out)
NetR270_1: R270.1 U1.C16(HOST_CLK_req)
NetR284_2: R284.2 U1.B15(SPIA_miso)

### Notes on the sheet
- Design Note:
- xWRL6844 CHIP -INTERFACE
- xWRL6844 CHIP -POWER
- 1. Antenna traces are GCPW traces
- 2. 'Generic No ERCs' were placed intentionally on Single Port RF Tx, Rx lines
- RADAR_SYNC_IN net is connected
- for the hardware trigger
- Review Note:
- Solder Jumper Added for H/W trigger
- Design Note
- Test point for 1V_RF_OUT to feed the 1V supply externally
- 40 MHz CRYSTAL OSCILLATOR
- DCA_LP_FTDI_HOST_INTR_1 is the SPI_BUSY signal
- Alternate Crystal part number : CX2016SA40000D0PTWC1

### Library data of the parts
C31 = CMP-0006356-2: as C48 on sheet PROC182A_USB_PWR_DC_Jack_Switch
C32 C33 = CMP-0006367-2: CAP, CERM, 4.7 pF, 50 V, +/- 2%, C0G/NP0, 0402; Manufacturer: MuRata; TaMin_C: -55°C; Polarized: N; SizeAreaWB_mm2: 3; Value1: Unknown; U/M: EA; Value: 4.7pF; TaMax_C: 125°C; SizeZ_mm: 0.6; SizeX_mm: 1; SizeY_mm: 0.5; Cap_Case: 0402; Value2: 50V; CompType: Capacitor; AEC Category: Q200
C134 = CMP-0078265-1: as C85 on sheet PROC182A_USB_PWR_DC_Jack_Switch
J15 = CMP-0080367-2: Solder Jumper, SMT; Manufacturer: NA
R81 R257 R267-R270 R284 = CMP-0002710-1: as R85 on sheet PROC182A_PMIC
R93 = CMP-0026299-2: RES, 33.2, 1%, 0.063 W, AEC-Q200 Grade 0, 0402; Manufacturer: Vishay-Dale; AEC Qualified: Y; Power_W: 63mW; SizeZ_mm: 0.6; TempCo: 100 ppm/C; VDC_V: 50V; AEC Category: Q200; AEC Grade: 0; EIA_Code: E96; SizeArea_mm2: 0.5; SizeX_mm: 1; Value2: 0.063W; Value_Code: 33R2
R146 R246 = CMP-0025950-3: RES, 100 k, 1%, 0.063 W, AEC-Q200 Grade 0, 0402; Manufacturer: Vishay-Dale; Power_W: 63mW; TempCo: 100 ppm/C; EIA_Code: E96; SizeX_mm: 1; SizeY_mm: 0.5; SizeZ_mm: 0.6; Value2: 0.063W; AEC Qualified: Y; VDC_V: 50V; AEC Category: Q200; AEC Grade: 0
R247 R250 R261 R276 = CMP-0025958-3: as R9 on sheet PROC182A_USB_PWR_DC_Jack_Switch
R255 R256 = CMP-0025950-3: as R11 on sheet PROC182A_PMIC
TP2 TP3 TP5 TP6 TP8 TP9 TP11 TP12 TP22 = CMP-0078143-3: TEST POINT.  No entry in BOM.
U1 = CMP-0124117-1: Single-Chip 57 to 64-GHz Automotive Radar Sensor; Manufacturer: Texas Instruments; AEC Category: Q200; CompType: IC; SizeZ_mm: 1.044mm; Bandwidth: 7GHz; Interface: I2C,SPI,UART,CAN,LIN,LVDS; Max Frequency: 64GHz; Number Of Adc Channels: 4; Number Of Gpio: 2; Standoff Height: 0.155mm; TJmax_C: +140°C
Y1 = CMP-0090505-1: 40MHz ±10ppm Crystal 8pF 50 Ohms 4-SMD, No Lead; Manufacturer: Diodes; Alternate Part Number: CX2016SA40000D0PTWC1; Frequency Stability: 50ppm; Esr: 50; AEC Qualified: Yes; AEC Grade: Grade 1; SizeZ_mm: 0.55mm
